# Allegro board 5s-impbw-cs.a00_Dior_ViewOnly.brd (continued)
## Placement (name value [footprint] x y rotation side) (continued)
PU7  -  [MX_QFN_20P_16_S118_PAD_4V]  110.82 61.81 90 top
PU8  -  [MX_QFN_16P_118X188_MPS]  119.6 6.59 270 bottom
PU9  -  [MX_SOT23_S5_H51]  46.91 11.39 270 bottom
Q1  -  [MX_SOT23]  52.9 65.16 0 bottom
Q2  -  [MX_SOT23_H43]  77.88 81.81 270 top
Q3  -  [MX_SOT363]  107.2 74.51 270 top
Q4  -  [MX_SOT23_H43]  116.1 67.62 270 bottom
Q5  -  [MX_SOT363]  181.63 68.02 90 bottom
Q6  -  [MX_SOT23_2D4_H51]  186.67 28.39 90 bottom
Q7  -  [MX_SOT363]  181.31 29.76 0 bottom
Q8  -  [MX_SOT23_H43]  127.37 81.66 270 top
Q9  -  [MX_SOT23_H43]  113.01 81.76 270 top
Q10  -  [MX_SOT23_H43]  115.51 72.71 270 top
Q11  -  [MX_SOT23_H43]  120.48 81.66 270 top
Q12  -  [MX_SOT23_H43]  111.14 72.7 270 top
Q13  -  [MX_SOT23_H43]  117.14 81.76 270 top
Q14  -  [MX_SOT23_H43]  123.79 81.66 270 top
Q15  -  [MX_SOT23_H43]  164.23 71.93 270 bottom
Q16  -  [MX_SOT23_H43]  167.46 71.93 270 bottom
Q19  -  [MX_SOT23_H43]  38.44 89.2 180 bottom
Q20  -  [MX_SOT23_H43]  11.13 73.5 90 bottom
Q21  -  [MX_SOT23_2D4_H44]  170.73 35.96 90 top
Q22  -  [MX_SOT23_H43]  173.5 31.9 270 top
Q23  -  [MX_SOT23_H43]  170.15 31.91 90 top
Q24  -  [MX_SOT23_2D4_H44]  178.18 70.95 0 bottom
Q25  -  [MX_SOT23_H43]  170.68 71.66 90 bottom
Q26  -  [MX_SOT23_H43]  173.93 71.66 90 bottom
Q27  -  [MX_SOT363]  173.08 69.38 0 top
Q28  -  [MX_SOT23_H43]  170.07 72.84 0 top
Q29  -  [MX_SOT363]  173.16 66.03 0 top
Q30  -  [MX_SOT363]  170.24 69.38 0 top
Q31  -  [MX_SOT363]  174.94 72.79 0 top
Q32  -  [MX_SOT23_H43]  177.91 72.35 90 top
Q33  -  [MX_SOT23_H43]  177.91 67.97 270 top
Q34  -  [MX_SOT23_H43]  61.31 9.69 180 bottom
Q35  -  [MX_SOT23_H43]  58.7 5.8 270 bottom
Q36  -  [MX_SOT23_H43]  160.31 38.94 90 top
Q37  -  [MX_SOT23_H43]  163.57 38.93 270 top
Q38  -  [MX_SOT23_H43]  119.35 67.97 270 bottom
Q39  -  [MX_SOT23_H43]  131.65 15.71 0 top
Q40  -  [MX_SOT363]  135.59 15.46 270 top
Q9200  -  [MX_SOT363]  156.57 61.3 90 top
Q9202  -  [MX_SOT23_H43]  144.57 78.87 90 top
R1  -  [MX_R0402]  74.53 49.17 180 top
R2  -  [MX_R0402]  76.76 47.46 270 top
R3  -  [MX_R0402]  84.2 45.74 90 top
R4  -  [MX_R0402]  76.99 49.45 0 top
R5  -  [MX_R0402]  78.82 44.09 90 top
R6  -  [MX_R0402]  83.72 50.23 0 top
R7  -  [MX_R0402]  80.82 48.28 270 top
R8  -  [MX_R0402]  81.87 48.28 270 top
R9  -  [MX_R0402]  75.67 47.46 270 top
R10  -  [MX_R0402]  88.75 50.46 0 top
R11  -  [MX_R0402]  88.75 51.5 0 top
R12  -  [MX_R0402]  73.28 47.57 270 top
R13  -  [MX_R0402]  88.75 47.26 0 top
R14  -  [MX_R0402]  77.83 47.46 270 top
R15  -  [MX_R0402]  88.75 48.33 0 top
R16  -  [MX_R0402]  88.75 45.03 0 top
R17  -  [MX_R0402]  88.75 46.12 0 top
R18  -  [MX_R0402]  86.97 43.15 270 top
R19  -  [MX_R0402]  79.69 49.32 270 top
R20  -  [MX_R0402]  85.45 44.01 270 top
R21  -  [MX_R0402]  73.89 44.59 180 top
R22  -  [MX_R0402]  88.75 49.39 0 top
R23  -  [MX_R0402]  88.72 43.15 270 top
R24  -  [MX_R0402]  73.89 43.5 180 top
R25  -  [MX_R0402]  77.74 44.09 90 top
R26  -  [MX_R0402]  78.65 49.57 270 top
R27  -  [MX_R0402]  70.85 49.41 270 top
R28  -  [MX_R0402]  71.94 49.41 270 top
R29  -  [MX_R0402]  81.41 50.23 0 top
R30  -  [MX_R0402]  86.64 29.43 0 top
R31  -  [MX_R0402]  81.26 44.11 90 top
R32  -  [MX_R0402]  90.83 58.08 270 top
R33  -  [MX_R0402]  86.64 70.81 0 top
R34  -  [MX_R0402]  86.64 30.45 0 top
R35  -  [MX_R0402]  80.21 44.11 90 top
R36  -  [MX_R0402]  90.8 60.38 90 top
R37  -  [MX_R0402]  86.64 71.9 0 top
R38  -  [MX_R0402]  86.98 22.39 90 top
R39  -  [MX_R0402_SHORT]  88.06 22.39 90 top
R40  -  [MX_R0402]  82.88 18.86 0 top
R41  -  [MX_R0402]  51.51 17.49 0 top
R42  -  [MX_R0402]  76.33 17.75 0 top
R43  -  [MX_R0402]  49.71 18.04 90 top
R44  -  [MX_R0402]  78.26 18.86 180 top
R45  -  [MX_R0402]  48.61 17.15 90 top
R46  -  [MX_R0402]  76.33 16.71 180 top
R47  -  [MX_R0402]  50.12 20.92 180 top
R56  -  [MX_R0402]  53.29 16.86 90 top
R57  -  [MX_R0402]  52.69 18.75 0 top
R59  -  [MX_R0402]  55.68 19.25 90 top
R60  -  [MX_R0402]  54.95 17.13 0 top
R61  -  [MX_R0402]  54.64 19.24 90 top
R62  -  [MX_R0402]  56.19 14.8 180 top
R63  -  [MX_R0402]  55.22 21.04 180 top
R66  -  [MX_R0402]  56.79 16.47 270 top
R69  -  [MX_R0402_SMALL]  169.55 80.03 270 bottom
R70  -  [MX_R0402_SMALL]  46.51 71.44 0 bottom
R71  -  [MX_R0402_SMALL]  24.87 74.03 270 bottom
R72  -  [MX_R0402_SMALL]  54.61 68.85 0 top
R73  -  [MX_R0402_SMALL]  48.46 68.8 180 top
R74  -  [MX_R0402]  48.59 69.82 180 top
R75  -  [MX_R0402_SMALL]  52.05 72.41 90 top
R76  -  [MX_R0402_SMALL]  52.16 68.34 0 top
R77  -  [MX_R0402]  48.77 67.85 0 top
R78  -  [MX_R0402_SMALL]  84.27 88.67 0 bottom
R79  -  [MX_R0402_SMALL]  29.57 71.7 90 top
R80  -  [MX_R0402_SMALL]  30.58 73.44 270 top
R81  -  [MX_R0402_SMALL]  28.12 74.15 270 bottom
R82  -  [MX_R0402_SMALL]  27.24 74.02 90 bottom
R83  -  [MX_R0402_SMALL]  35.47 74.45 90 bottom
R84  -  [MX_R0402_SMALL]  30.12 74.8 90 bottom
R85  -  [MX_R0402_SMALL]  30.41 71.7 90 top
R86  -  [MX_R0402_SMALL]  28.35 72.06 90 bottom
R87  -  [MX_R0402_SMALL]  27.28 71.92 90 bottom
R88  -  [MX_R0402_SMALL]  56.4 63.5 90 bottom
R89  -  [MX_R0402_SMALL]  56.41 66.41 90 bottom
R91  -  [MX_R0402_SMALL]  39.56 74.75 270 bottom
R92  -  [MX_R0402_SMALL]  26.41 74.02 270 bottom
R93  -  [MX_R0402_SMALL]  15.85 75.84 270 top
R94  -  [MX_R0402_SMALL]  16.67 75.84 270 top
R95  -  [MX_R0402_SMALL]  15.02 75.84 90 top
R96  -  [MX_R0402_SMALL]  26.46 71.92 90 bottom
R97  -  [MX_R0402_SMALL]  15.84 73.46 90 top
R98  -  [MX_R0402_SMALL]  16.67 73.46 90 top
R99  -  [MX_R0402_SMALL]  14.99 73.46 270 top
R103  -  [MX_R0402_SMALL]  23.87 71.84 90 bottom
R106  -  [MX_R0402_SMALL]  22.96 71.84 90 bottom
R108  -  [MX_R0402_SMALL]  43 61.69 0 top
R109  -  [MX_R0402_SMALL]  44.63 71.83 270 bottom
R110  -  [MX_R0402_SMALL]  27.13 71.75 90 top
R114  -  [MX_R0402_SMALL]  29.71 23.98 90 top
R119  -  [MX_R0402_SMALL]  43.81 71.83 270 bottom
R124  -  [MX_R0402_SMALL]  171.25 25.01 90 top
R125  -  [MX_R0402_SMALL]  171.25 23.39 270 top
R127  -  [MX_R0402_SMALL]  170.39 25.01 270 top
R128  -  [MX_R0402_SMALL]  170.4 23.39 90 top
R129  -  [MX_R0402]  159.39 34.15 180 top
R130  -  [MX_R0402]  159.55 14.32 90 top
R131  -  [MX_R0402]  160.76 32.17 270 top
R132  -  [MX_R0402]  170.61 26.87 180 top
R133  -  [MX_R0402_SMALL]  160.5 29.6 90 top
R134  -  [MX_R0402_SMALL]  161.85 32.22 270 top
R135  -  [MX_R0402]  168.59 19.86 180 top
R136  -  [MX_R0402_SMALL]  168.59 17.99 180 top
R137  -  [MX_R0402]  168.61 20.91 180 top
R138  -  [MX_R0402_SMALL]  168.62 18.89 180 top
R144  -  [MX_R0402_SMALL]  160.76 81.58 270 bottom
R145  -  [MX_R0402_SMALL]  171.35 84.12 0 top
R146  -  [MX_R0402_SMALL]  136.73 12.03 270 top
R148  -  [MX_R0402_SMALL]  7.27 81.09 270 top
R164  -  [MX_R0402_SMALL]  132.61 32.27 90 top
R165  -  [MX_R0402_SMALL]  131.75 32.28 270 top
R166  -  [MX_R0402_SMALL]  130.81 32.28 270 top
R167  -  [MX_R0402_SMALL]  129.09 32.31 270 top
R168  -  [MX_R0402_SMALL]  128.1 32.31 270 top
R169  -  [MX_R0402_SMALL]  127.23 32.31 270 top
R170  -  [MX_R0402_SMALL]  123.98 32.28 270 top
R171  -  [MX_R0402_SMALL]  123.06 32.28 270 top
R172  -  [MX_R0402_SMALL]  122.2 32.28 270 top
R173  -  [MX_R0402_SMALL]  107.14 80.99 0 top
R174  -  [MX_R0402]  104.17 75.93 0 top
R175  -  [MX_R0402]  102.92 81.35 0 top
R176  -  [MX_R0402_SMALL]  95.23 71.01 0 bottom
R177  -  [MX_R0402_SHORT_SMALL]  106.97 71.01 270 bottom
R178  -  [MX_R0402_SMALL]  95.56 79.54 0 top
R179  -  [MX_R0603_SMALL]  119.1 73 180 bottom
R180  -  [MX_R0603_SMALL]  115.03 85.03 90 top
R181  -  [MX_R0402_SMALL]  95.84 87.42 180 bottom
R182  -  [MX_R0402_SMALL]  95.56 78.72 0 top
R183  -  [MX_R0402_SMALL]  95.96 77.85 0 top
R184  -  [MX_R0402_SMALL]  104.52 81.25 90 top
R185  -  [MX_R0402_SMALL]  95.96 76.99 0 top
R186  -  [MX_R0402_SMALL]  95.96 76 0 top
R187  -  [MX_R0402_SHORT_SMALL]  93.68 81.6 180 top
R188  -  [MX_R0402_SMALL]  96.68 76.62 90 bottom
R189  -  [MX_R0402_SMALL]  93.8 83.41 180 bottom
R190  -  [MX_R0402_SMALL]  101.13 70.91 270 bottom
R191  -  [MX_R0402_SMALL]  102.84 71.01 90 bottom
R192  -  [MX_R0402_SHORT_SMALL]  93.68 82.45 180 top
R193  -  [MX_R0402_SMALL]  116.36 71.56 180 bottom
R194  -  [MX_R0402_SMALL]  116.36 70.64 180 bottom
R195  -  [MX_R0402_SMALL]  108.64 71.01 90 bottom
R196  -  [MX_R0402_SMALL]  107.8 71.01 90 bottom
R197  -  [MX_R0402_SMALL]  105.32 71.01 90 bottom
R198  -  [MX_R0402_SMALL]  104.5 71.01 90 bottom
R199  -  [MX_R0402_SMALL]  108.97 80.04 0 top
R200  -  [MX_R0402_SMALL]  108.97 79.13 0 top
R201  -  [MX_R0402_SMALL]  108.97 81.01 0 top
R202  -  [MX_R0402_SMALL]  103.68 71.01 90 bottom
R203  -  [MX_R0402_SMALL]  117.12 74.63 180 bottom
R204  -  [MX_R0402_SMALL]  117.12 73.59 180 bottom
R205  -  [MX_R0402_SMALL]  112.83 71.01 270 bottom
R206  -  [MX_R0402_SMALL]  101.64 74.09 90 top
R207  -  [MX_R0402_SMALL]  117.12 72.63 180 bottom
R208  -  [MX_R0402_SMALL]  102.68 74.09 270 top
R210  -  [MX_R0402_SMALL]  96.88 72.03 0 bottom
R211  -  [MX_R0402_SMALL]  96.88 72.86 180 bottom
R212  -  [MX_R0402_SMALL]  94.57 73.55 90 bottom
R213  -  [MX_R0402_SMALL]  111.99 71.02 90 bottom
R214  -  [MX_R0402_SMALL]  110.28 70.98 90 bottom
R215  -  [MX_R0402_SMALL]  111.15 71.02 90 bottom
R216  -  [MX_R0402_SMALL]  95.4 73.55 90 bottom
R217  -  [MX_R0402_SMALL]  98.91 80.03 180 top
R218  -  [MX_SHORTPIN_RECTANGLE_LF3]  114.25 63.61 270 bottom
R219  -  [MX_R0402_SMALL]  105.07 65.04 90 bottom
R220  -  [MX_R0402_SMALL]  105.12 67.2 90 bottom
R221  -  [MX_R0402_SMALL]  113.98 65.68 90 bottom
R222  -  [MX_R0402_SMALL]  109.46 70.77 270 bottom
R223  -  [MX_R0402_SMALL]  92.99 71.65 0 top
R224  -  [MX_R0402_SMALL]  117.53 75.91 270 bottom
R225  -  [MX_R0402_SMALL]  116.41 80.43 270 bottom
R226  -  [MX_R0402]  72.98 77.82 0 top
R227  -  [MX_R0402]  72.95 79 0 top
R228  -  [MX_R0402]  104.98 74.26 270 top
R229  -  [MX_R0402]  106.98 69.12 180 top
R230  -  [MX_R0402]  116.15 64.6 0 bottom
R231  -  [MX_R0805_SHORT_SMALL]  180.12 64.45 0 top
R232  -  [MX_R0402_SMALL]  183.57 62.95 270 top
R233  -  [MX_R0805_SHORT_SMALL]  181.84 58.84 270 top
R234  -  [MX_R0402_SMALL]  183.57 54.3 270 top
R235  -  [MX_R0402_SMALL]  183.8 67.5 270 bottom
R236  -  [MX_R0402_SMALL]  183.21 27.86 270 bottom
R237  -  [MX_R0402]  127.79 84.45 0 top
R238  -  [MX_R0402]  112.55 84.53 0 top
R239  -  [MX_R0402]  117.88 75.79 0 top
R240  -  [MX_R0402]  121.62 75.91 180 top
R241  -  [MX_R0402]  113.31 73.65 270 top
R242  -  [MX_R0402]  120.8 84.47 0 top
R243  -  [MX_R0402]  110.39 75.39 0 top
R244  -  [MX_R0402_SMALL]  109.17 68.96 0 top
R245  -  [MX_R0402]  117.63 84.47 0 top
R246  -  [MX_R0402]  124.28 84.47 0 top
R247  -  [MX_R0402_SMALL]  148.56 87.57 270 bottom
R248  -  [MX_R0402_SMALL]  148.56 89.15 270 bottom
R249  -  [MX_R0402]  148.46 80.84 90 bottom
R250  -  [MX_R0402_SMALL]  148.56 82.8 90 bottom
R251  -  [MX_R0402_SMALL]  167.16 68.39 180 bottom
R252  -  [MX_R0402_SMALL]  168.37 68.85 90 bottom
R253  -  [MX_R0402_SMALL]  164.24 68.37 180 bottom
R254  -  [MX_R0402_SMALL]  165.7 68.83 90 bottom
R255  -  [MX_R0402_SMALL]  166.7 74.57 0 bottom
R256  -  [MX_R0402_SMALL]  163.4 74.55 0 bottom
R257  -  [MX_R0402_SMALL]  167.16 69.24 0 bottom
R258  -  [MX_R0402_SMALL]  168.35 74.58 180 bottom
R259  -  [MX_R0402_SMALL]  164.24 69.21 0 bottom
R260  -  [MX_R0402_SMALL]  165.05 74.53 180 bottom
R273  -  [MX_R0603_SMALL]  37.69 86.56 180 bottom
R274  -  [MX_R0603_SMALL]  37.69 85.35 180 bottom
R275  -  [MX_R0402]  42.15 87.9 180 bottom
R276  -  [MX_R0402]  16.24 65.84 270 bottom
R277  -  [MX_R0402]  16.29 63.49 90 bottom
R278  -  [MX_R0402]  20.5 61.13 90 top
R279  -  [MX_R0402_SMALL]  103.05 19.84 180 top
R280  -  [MX_R0402_SMALL]  103.05 17.98 180 top
R281  -  [MX_R0402_SMALL]  103.05 18.85 180 top
R282  -  [MX_R0603_SHORT_SMALL]  102.92 8.15 90 bottom
R284  -  [MX_R0402_SHORT_SMALL]  153.45 11.98 90 top
R285  -  [MX_R0402_SHORT_SMALL]  152.54 11.98 90 top
R286  -  [MX_R0402_SMALL]  164.89 16.02 90 top
R288  -  [MX_R0402_SMALL]  174.21 18.18 90 top
R289  -  [MX_R0402]  174.21 15.92 90 top
R290  -  [MX_R0402_SMALL]  157.6 29.61 270 top
R291  -  [MX_R0402]  173.01 15.92 90 top
R293  -  [MX_R0402_SMALL]  173.02 18.18 90 top
R294  -  [MX_R0805_SMALL]  171.56 38.6 0 top
R295  -  [MX_R0805_SMALL]  167.64 12.18 180 top
R296  -  [MX_R0402]  169.61 14.01 90 top
R297  -  [MX_R0402_SMALL]  183.17 34.64 180 bottom
R298  -  [MX_R0402]  170.65 14.01 90 top
R299  -  [MX_R0603]  173.5 35.57 270 top
R300  -  [MX_R0402]  183.59 32.99 90 bottom
R301  -  [MX_R0402_SMALL]  158.6 29.59 90 top
R302  -  [MX_R0603]  181.05 33.24 270 bottom
R304  -  [MX_R0402]  182.45 32.99 270 bottom
R305  -  [MX_R0402]  175.39 62.78 0 top
R306  -  [MX_R0402_SMALL]  176.2 58.03 270 top
R307  -  [MX_R0402_SMALL]  177.45 56.71 270 top
R308  -  [MX_R0402_SMALL]  173.59 58.54 180 top
R309  -  [MX_R0402_SMALL]  173.59 59.38 180 top
R310  -  [MX_R0402_SMALL]  175.95 72.92 90 bottom
R311  -  [MX_R0402_SMALL]  175.94 71.29 270 bottom
R312  -  [MX_L1206_H51]  176.68 66.11 270 bottom
R313  -  [MX_R0402]  172.88 72.41 270 top
R314  -  [MX_R0402]  168.3 70.02 90 top
R315  -  [MX_R0402]  175.06 67.61 90 top
R316  -  [MX_R0402]  171.17 66.08 90 top
R318  -  [MX_R0402]  170 66.08 90 top
R319  -  [MX_R0402]  174.19 75.02 180 top
R320  -  [MX_R0402]  180.17 71.65 270 top
R321  -  [MX_R0402]  175.77 69.77 90 top
R322  -  [MX_R0402]  180.06 69.13 90 top
R323  -  [MX_R0402_SMALL]  20.17 84.76 180 top
R324  -  [MX_R0402_SMALL]  20.17 85.59 180 top
R325  -  [MX_R0402_SMALL]  29.26 83.46 90 top
R326  -  [MX_R0402_SMALL]  27.67 83.07 180 top
R327  -  [MX_R0402_SMALL]  20.03 81.98 270 top
R328  -  [MX_R0402_SMALL]  20.92 81.98 270 top
R329  -  [MX_R0402_SMALL]  27.92 84.96 0 top
R330  -  [MX_R0402_SMALL]  27.92 84.13 0 top
R331  -  [MX_R0402_SMALL]  31.71 81.17 90 top
R332  -  [MX_R0402_SMALL]  40.92 85.04 180 top
R333  -  [MX_R0402_SMALL]  40.77 83.8 180 top
R334  -  [MX_R0402_SMALL]  39.6 82.81 180 top
R335  -  [MX_R0402_SMALL]  30.8 83.24 180 top
R336  -  [MX_R0402_SMALL]  30.8 82.39 180 top
R337  -  [MX_R0402_SMALL]  39.12 85.2 0 top
R338  -  [MX_R0402_SMALL]  39.12 83.89 0 top
R339  -  [MX_R0402_SMALL]  59.05 11.79 180 bottom
R340  -  [MX_R0402_SMALL]  58.18 8.42 0 bottom
R341  -  [MX_R0402_SMALL]  60.86 6.99 270 bottom
R342  -  [MX_R0402_SMALL]  61.25 5.64 0 bottom
R343  -  [MX_R0402_SMALL]  157.68 36.29 180 top
R344  -  [MX_R0402_SMALL]  161.62 36.29 0 top
R345  -  [MX_R0402_SMALL]  161.69 41.64 180 top
R346  -  [MX_R0402_SMALL]  163.4 36.29 0 top
R347  -  [MX_R0402]  122.12 70.91 90 bottom
R348  -  [MX_R0402_SMALL]  123.06 70.91 270 bottom
R349  -  [MX_R0402]  131.27 12.16 90 top
R350  -  [MX_R0402]  133.55 12.16 270 top
R351  -  [MX_R0402_SMALL]  134.7 12.03 270 top
R352  -  [MX_R0402_SMALL]  135.71 12.03 270 top
R353  -  [MX_R0402]  132.41 12.16 90 top
R354  -  [MX_R0402_SMALL]  178.21 80.15 90 bottom
R355  -  [MX_R0402_SMALL]  177.55 81.86 0 bottom
R356  -  [MX_R0402_SMALL]  178.16 77.77 270 bottom
R357  -  [MX_R0402_SMALL]  179.15 81.86 0 bottom
R358  -  [MX_R0402_SMALL]  179.02 75.58 270 bottom
R359  -  [MX_R0402_SMALL]  179.53 78.33 180 bottom
R360  -  [MX_R0402_SMALL]  175.34 84.37 270 bottom
R369  -  [MX_R0402_SMALL]  150.37 77.28 0 bottom
R370  -  [MX_R0402_SMALL]  159.03 67.96 90 top
R371  -  [MX_R0402_SMALL]  158.17 67.96 90 top
R376  -  [MX_R0402_SMALL]  182.96 49.34 180 top
R377  -  [MX_R0402]  180.7 52.93 0 top
R378  -  [MX_R0402_SMALL]  170.26 52.93 0 top
R379  -  [MX_R0402_SMALL]  170.26 49.88 0 top
R380  -  [MX_R0402_SMALL]  170.26 50.89 0 top
R381  -  [MX_R0402_SMALL]  170.26 51.91 0 top
R382  -  [MX_R0402_SMALL]  173.05 52.93 180 top
R383  -  [MX_R0402_SMALL]  173.05 49.88 180 top
R384  -  [MX_R0402_SMALL]  173.05 50.89 180 top
R385  -  [MX_R0402_SMALL]  173.05 51.91 180 top
R386  -  [MX_R0402_SMALL]  182.96 50.18 180 top
R387  -  [MX_R0402_SMALL]  182.96 51.07 180 top
R388  -  [MX_R0402_SMALL]  180.71 51.02 0 top
R389  -  [MX_R0402_SMALL]  180.71 51.91 0 top
R400  -  [MX_R0402_SMALL]  34.95 72.02 90 bottom
R401  -  [MX_R0402_SMALL]  28.73 71.7 90 top
R405  -  [MX_R0402_SMALL]  40.44 74.74 270 bottom
R406  -  [MX_R0402]  41.66 72.2 90 bottom
R407  -  [MX_R0402]  39.07 72.24 90 bottom
R410  -  [MX_R0402]  138.13 74.05 270 top
R414  -  [MX_R0402_SMALL]  161.6 85.4 0 top
R415  -  [MX_R0402_SMALL]  22.98 74.29 270 bottom
R416  -  [MX_R0402_SMALL]  21.99 76.97 270 top
R425  -  [MX_R0402_SMALL]  24.81 81.38 180 bottom
R426  -  [MX_R0402_SMALL]  149.9 7.13 0 top
R427  -  [MX_R0402_SMALL]  183.72 14.91 90 bottom
R428  -  [MX_R0402_SMALL]  161.05 73.29 270 top
R429  -  [MX_R0402_SMALL]  150.64 71.23 180 bottom
R430  -  [MX_R0402_SMALL]  157.93 74.81 270 top
R431  -  [MX_R0402]  160.1 68.04 270 top
R432  -  [MX_R0402]  167.38 67.2 90 top
R433  -  [MX_R0402]  172.04 62.61 0 top
R434  -  [MX_R0402_SMALL]  80.33 87.88 180 bottom
R435  -  [MX_R0402_SMALL]  77.62 87.17 180 bottom
R436  -  [MX_R0402]  165.69 66.77 0 top
R437  -  [MX_R0603]  123.19 68.95 180 top
R440  -  [MX_R0402_SMALL]  121.36 32.28 270 top
R450  -  [MX_R0402_SMALL]  175.78 56.51 180 top
R455  -  [MX_R0402_SMALL]  101.98 70.91 90 bottom
R456  -  [MX_R0402_SMALL]  99.75 70.49 0 bottom
R457  -  [MX_R0402_SMALL]  116.72 77.16 0 bottom
R9203  -  [MX_R0402_SMALL]  139.53 77.04 0 top
R9204  -  [MX_R0402_SMALL]  153.26 65.03 90 top
R9330  -  [MX_R0402_SMALL]  32.9 72.35 270 bottom
R60358  -  [MX_R0402_SMALL]  156.61 29.61 270 top
R60359  -  [MX_R0402_SMALL]  10.25 75.73 270 top
R60362  -  [MX_R0402_SMALL]  11.3 76.15 270 top
R60364  -  [MX_R0402]  12.52 75.57 90 top
R60365  -  [MX_R0402]  14.02 75.6 90 top
R60368  -  [MX_R0402_SMALL]  154.94 78.46 180 bottom
R60369  -  [MX_R0402_SMALL]  154.94 79.38 180 bottom
R60370  -  [MX_R0402_SMALL]  155.23 68.05 90 top
R60371  -  [MX_R0402_SMALL]  154.32 68.05 90 top
R60464  -  [MX_R0402_SMALL]  32.42 74.22 90 bottom
R60465  -  [MX_R0402]  139.42 78.03 0 top
R60466  -  [MX_R0402]  139.56 79.19 180 top
R60467  -  [MX_R0402]  139.56 80.28 180 top
R60468  -  [MX_R0402]  139.56 81.38 180 top
R60469  -  [MX_R0402]  138.13 76.38 270 top
R60471  -  [MX_R0402_SMALL]  128.94 44.97 270 top
R60472  -  [MX_R0402_SMALL]  173.13 56.46 90 top
R60473  -  [MX_R0402_SMALL]  173.99 56.46 90 top
R60474  -  [MX_R0402_SMALL]  8.51 85.56 0 top
R60475  -  [MX_R0402_SMALL]  8.51 84.68 0 top
R60476  -  [MX_R0402_SMALL]  178.28 56.71 270 top
R60477  -  [MX_R0402_SMALL]  24.08 9.85 180 bottom
RN1  -  [MX_2R4P0402]  48.03 72.88 180 top
RN3  -  [MX_2R4P0402]  49.65 72.82 180 top
RN4  -  [MX_4R8P0402]  25.37 71.78 180 top
RN6  -  [MX_2R4P0603]  161.68 85.34 180 bottom
RN7  -  [MX_2R4P0603]  33.95 89.04 90 bottom
RN8  -  [MX_2R4P0402_H18]  44.38 70.58 0 top
S1C1  -  [MX_C0402]  165.51 46.74 180 top
S1C2  -  [MX_C0402]  165.51 47.92 180 top
S1C3  -  [MX_C0402]  167.76 49.23 0 top
S1C4  -  [MX_C0402]  167.76 50.33 0 top
S1C5  -  [MX_C0402]  167.77 51.47 0 top
S1C6  -  [MX_C0402]  167.77 52.61 0 top
S1C7  -  [MX_C0402]  167.74 53.71 180 top
S1C8  -  [MX_C0402]  167.74 54.78 180 top
S1C9  -  [MX_C0402]  167.74 55.91 180 top
S1C10  -  [MX_C0402]  167.74 57 180 top
S1R4  -  [MX_R0402]  162.14 46.76 0 top
S1R5  -  [MX_R0402]  162.13 47.91 180 top
SC1  -  [MX_C0402_SMALL]  34.05 67.87 90 top
SC2  -  [MX_C0402_SMALL]  93.68 79.98 180 top
SC3  -  [MX_C0402_SMALL]  99.93 72.59 0 bottom
SC4  -  [MX_C0402_SMALL]  95.8 84.69 0 bottom
SC5  -  [MX_C0402_SMALL]  97.03 82.14 0 bottom
SC6  -  [MX_C0402_SMALL]  114.73 75.94 180 top
SC7  -  [MX_C0402]  102.49 11.12 180 bottom
SC8  -  [MX_C0402_SMALL]  180.85 54.7 180 top
SC9  -  [MX_C0402_SMALL]  180.84 53.87 180 top
SC10  -  [MX_C0402_SMALL]  180.27 59.5 270 top
SC11  -  [MX_C0402_SMALL]  179.4 59.5 270 top
SC12  -  [MX_C0402]  175.54 62.91 0 bottom
SC13  -  [MX_C0402_SMALL]  22.93 81.07 270 top
SC14  -  [MX_C0402_SMALL]  16.03 83.28 0 top
SC15  -  [MX_C0402_SMALL]  23.77 81.07 270 top
SC16  -  [MX_C0402_SMALL]  16.03 84.09 0 top
SC17  -  [MX_C0402_SMALL]  24.7 81.04 90 top
SC18  -  [MX_C0402_SMALL]  25.61 81.04 90 top
SC19  -  [MX_C0402_SMALL]  33.85 79.78 90 top
SC20  -  [MX_C0402_SMALL]  31.08 86.24 0 top
SC21  -  [MX_C0402_SMALL]  34.71 79.78 90 top
SC22  -  [MX_C0402_SMALL]  31.08 87.06 0 top
SC23  -  [MX_C0402_SMALL]  35.78 79.64 270 top
SC24  -  [MX_C0402_SMALL]  36.64 79.64 270 top
SP1  -  [MX_R0402_SHORT_SMALL]  117.27 85.87 180 bottom
SQ1  -  [MX_SOT363]  69.78 88.21 90 bottom
SQ2  -  [MX_SOT363]  73.49 88.21 270 bottom
SR1  -  [MX_R0402_SMALL]  55.02 63.14 180 bottom
SR2  -  [MX_R0402_SMALL]  55.55 66.34 90 bottom
SR3  -  [MX_R0402]  29.73 72.19 270 bottom
SR4  -  [MX_R0402]  22.04 74.68 90 bottom
SR7  -  [MX_R0402]  10.62 72.1 180 top
SR8  -  [MX_R0402]  29.19 75.32 90 bottom
SR9  -  [MX_R0402_SMALL]  84.14 87.84 180 bottom
SR10  -  [MX_R0402]  17.96 52.68 270 top
SR13  -  [MX_R0402_SMALL]  32.19 74.8 270 top
SR14  -  [MX_R0402_SMALL]  27.15 73.4 270 top
SR15  -  [MX_R0402]  19.61 24.96 180 top
SR16  -  [MX_R0402]  23.01 74.22 270 top
SR18  -  [MX_R0402]  19.2 23.18 90 top
SR19  -  [MX_R0402]  50.45 56.38 0 bottom
SR21  -  [MX_R0402]  23.56 71.7 90 top
SR27  -  [MX_R0402]  30.91 72.46 270 bottom
SR28  -  [MX_R0402]  34.88 77.18 270 top
SR29  -  [MX_R0402_SMALL]  103.56 74.08 270 top
SR35  -  [MX_R0402]  32.81 71.82 270 top
SR36  -  [MX_R0402]  42.15 76.3 270 top
SR50  -  [MX_R0402]  23.91 74.19 270 bottom
SR51  -  [MX_R0402]  35.44 76.76 90 bottom
SR52  -  [MX_R0402]  33.78 72.18 270 bottom
SR59  -  [MX_R0402]  36.47 76.75 270 bottom
SR60  -  [MX_R0402]  34.44 74.82 90 bottom
SR61  -  [MX_R0402]  30.42 78.56 90 bottom
SR62  -  [MX_R0402]  32.49 78.56 270 bottom
SR63  -  [MX_R0402]  31.46 78.56 90 bottom
SR70  -  [MX_R0402]  43.84 78.38 270 top
SR71  -  [MX_R0402]  66.96 87.42 180 bottom
SR72  -  [MX_R0402]  70.87 90.11 0 bottom
SR73  -  [MX_R0402]  69.57 86.38 0 bottom
SR74  -  [MX_R0402]  68.43 90.11 180 bottom
SR75  -  [MX_R0402]  73.43 90.11 0 bottom
SR76  -  [MX_R0402]  73.1 86.3 180 bottom
SR77  -  [MX_R0402_SMALL]  159.92 81.58 90 bottom
SR78  -  [MX_R0402_SMALL]  42.98 71.87 90 bottom
SR79  -  [MX_R0402_SMALL]  41.72 74.45 270 bottom
SR80  -  [MX_R0402_SMALL]  41.22 76.04 270 top
SR81  -  [MX_R0402_SMALL]  41.88 72.26 270 top
SR82  -  [MX_R0402_SMALL]  37.09 72.12 270 bottom
SR85  -  [MX_R0402]  23.38 76.9 270 top
SR86  -  [MX_R0402]  22.49 71.69 90 top
SR87  -  [MX_R0402]  21.43 71.69 270 top
SR88  -  [MX_R0402]  24.08 74.2 270 top
SR89  -  [MX_R0402]  19.29 71.65 90 top
SR90  -  [MX_R0402]  19.35 73.95 270 top
SR97  -  [MX_R0402]  48.11 78.64 90 top
SR9206  -  [MX_R0402_SHORT_SMALL]  156.82 64.25 180 top
SR9208  -  [MX_R0402_SMALL]  164.25 85.82 180 top
SR9209  -  [MX_R0402]  26.06 75.26 90 top
SR9210  -  [MX_R0402]  31.4 60.31 270 top
ST1  -  [MX_TPC26B_S4_68]  21.82 60.52 180 bottom
ST2  -  [MX_TPC26B_S4_68]  21.79 62.32 180 bottom
ST3  -  [MX_TPC26B_S4_68]  31.78 49.34 180 bottom
ST4  -  [MX_TPC26B_S4_68]  32.31 54.93 180 bottom
ST8  -  [MX_TPC26B_S4_68]  186.44 26.04 0 top
ST9  -  [MX_TPC26B_S4_68]  111.56 52.14 0 top
ST14  -  [MX_TPC26B_S4_68]  25.66 65.4 180 bottom
ST15  -  [MX_TPC26B_S4_68]  27.38 66.24 180 bottom
ST16  -  [MX_TPC26B_S4_68]  25.07 70.86 0 top
ST18  -  [MX_TPC26B_S4_68]  26.57 67.86 180 bottom
ST19  -  [MX_TPC26B_S4_68]  23.67 68.19 180 bottom
ST20  -  [MX_TPC26B_S4_68]  21.64 70.83 0 top
ST21  -  [MX_TPC26B_S4_68]  25.02 67.01 180 bottom
ST22  -  [MX_TPC26B_S4_68]  23.75 69.97 180 bottom
ST24  -  [MX_TPC26B_S4_68]  23.78 65.47 180 bottom
ST27  -  [MX_TPC26B_S4_68]  20.17 69.92 180 bottom
ST28  -  [MX_TPC26B_S4_68]  21.67 72.71 0 top
ST29  -  [MX_TPC26B_S4_68]  33.86 82.39 0 top
ST30  -  [MX_TPC26B_S4_68]  123.39 38.45 0 top
ST31  -  [MX_TPC26B_S4_68]  125.3 38.96 0 top
ST32  -  [MX_TPC26B_S4_68]  120.73 40.99 0 top
ST33  -  [MX_TPC26B_S4_68]  141.56 73.63 0 top
ST34  -  [MX_TPC26B_S4_68]  5.92 68.8 0 top
ST35  -  [MX_TPC26B_S4_68]  5.67 54.07 0 top
ST36  -  [MX_TPC26B_S4_68]  5.67 52.04 0 top
ST37  -  [MX_TPC26B_S4_68]  5.54 49.12 0 top
ST38  -  [MX_TPC26B_S4_68]  15.44 35.53 180 bottom
ST39  -  [MX_TPC26B_S4_68]  11.63 35.91 180 bottom
ST40  -  [MX_TPC26B_S4_68]  135.71 58.26 180 bottom
ST41  -  [MX_TPC26B_S4_68]  111.58 50.13 0 top
ST42  -  [MX_TPC26B_S4_68]  137.36 39.72 0 top
ST43  -  [MX_TPC26B_S4_68]  179.02 65.75 0 top
SW1  -  [MX_SW_5P_315X244_H98]  151.76 82.46 0 top
T1  -  [MX_TPC26B_S4_68]  50.57 67.84 180 bottom
T2  -  [MX_TPC26B_S4_68]  46.25 65.12 0 top
T3  -  [MX_TPC26B_S4_68]  46.86 69 180 bottom
T4  -  [MX_TPC26B_S4_68]  25.3 55.24 180 bottom
T5  -  [MX_TPC26B_S4_68]  27.03 54.93 180 bottom
T8  -  [MX_TPC26B_S4_68]  31.93 67.68 180 bottom
T9  -  [MX_TPC26B_S4_68]  26.84 63.09 180 bottom
T10  -  [MX_TPC26B_S4_68]  25.79 75.4 0 top
T25  -  [MX_TPC26B_S4_68]  111.13 78.68 180 bottom
T27  -  [MX_TPC26B_S4_68]  109.27 89.1 180 bottom
T28  -  [MX_TPC26B_S4_68]  111.02 89.12 180 bottom
T29  -  [MX_TPC26B_S4_68]  182.42 65.42 0 top
T30  -  [TPC85B_68]  181.31 18.38 0 top
T31  -  [MX_TPC26B_S4_68]  186.89 23.28 180 bottom
T32  -  [MX_TPC26B_S4_68]  172.01 67.51 0 top
T33  -  [MX_TPC26B_S4_68]  40.36 87.01 0 top
T34  -  [TPC85B_68]  137.57 69.66 180 bottom
T35  -  [MX_TPC26B_S4_68]  20.76 80.49 180 bottom
T36  -  [MX_TPC26B_S4_68]  27.15 82.01 180 bottom
T37  -  [MX_TPC26B_S4_68]  31.64 82.24 0 top
T38  -  [MX_TPC26B_S4_68]  39.04 81.45 0 top
T39  -  [MX_TPC26B_S4_68]  133.17 72.41 180 bottom
T40  -  [MX_TPC26B_S4_68]  133.45 74.26 180 bottom
T41  -  [MX_TPC26B_S4_68]  137.39 75.02 0 top
T42  -  [MX_TPC26B_S4_68]  135.87 72.18 180 bottom
T43  -  [MX_TPC26B_S4_68]  128.58 76.47 180 bottom
T44  -  [MX_TPC26B_S4_68]  128.55 78.63 180 bottom
T45  -  [MX_TPC26B_S4_68]  127.03 75.67 180 bottom
T46  -  [MX_TPC26B_S4_68]  128.02 4.56 0 top
T47  -  [MX_TPC26B_S4_68]  124.66 4.06 0 top
T48  -  [MX_TPC26B_S4_68]  141.05 10.51 0 top
T49  -  [MX_TPC26B_S4_68]  139.22 10.51 0 top
T50  -  [MX_TPC26B_S4_68]  142.85 10.46 0 top
T51  -  [MX_TPC26B_S4_68]  125.5 78.55 180 bottom
T52  -  [MX_TPC26B_S4_68]  139.27 73.63 0 top
T53  -  [TPC85B_68]  114.63 36.16 0 top
T54  -  [MX_TPC26B_S4_68]  107.44 79.62 180 bottom
T58  -  [MX_TPC26B_S4_68]  129.06 71.62 180 bottom
T59  -  [MX_TPC26B_S4_68]  118.49 70.73 180 bottom
T60  -  [MX_TPC26B_S4_68]  119.28 68.95 180 bottom
T61  -  [MX_TPC26B_S4_68]  137.71 47.09 180 bottom
T62  -  [MX_TPC26B_S4_68]  32.79 69.31 180 bottom
T63  -  [MX_TPC26B_S4_68]  34.06 70.35 0 top
T65  -  [MX_TPC26B_S4_68]  16.92 60.98 180 bottom
T70  -  [MX_TPC26B_S4_68]  17.53 64.97 180 bottom
T71  -  [MX_TPC26B_S4_68]  178.26 82.02 180 bottom
T72  -  [MX_TPC26B_S4_68]  176.86 77.82 180 bottom
T9200  -  [MX_TPC26B_S4_68]  136.86 74.64 180 bottom
T9206  -  [MX_TPC26B_S4_68]  158.29 64.61 180 bottom
T9207  -  [MX_TPC26B_S4_68]  152.25 65.3 180 bottom
T9208  -  [TPC85B_68]  173.6 76.24 0 top
U1  -  [MX_BGA_1168P_30_1575X945]  31.83 48.49 90 bottom
U2  -  [MX_BGA_96P_31_524X433_COLAY]  77.98 25.41 0 top
U3  -  [MX_BGA_96P_31_524X433_COLAY]  77.98 36.94 0 top
U4  -  [MX_BGA_96P_31_524X433_COLAY]  77.98 56.75 0 top
U5  -  [MX_BGA_96P_31_524X433_COLAY]  77.98 68.29 0 top
U6  -  [MX_QFN_64P_16_S315_PAD_ANA]  162.29 22.92 180 top
U9  -  [MX_SOIC_28P_26_386X252]  127.95 38.64 180 top
U10  -  [MX_QFP_128P_16_630X630]  106.78 81.93 90 bottom
U11  -  [MX_SOIC_8P_50_197X236]  109.62 66.96 90 bottom
U12  -  [MX_SOIC_8P_26_122X193_H48]  74.22 82.98 180 top
U13  -  [MX_QFN_24P_20_S157_PAD_IN]  24.08 85.04 270 top
U14  -  [MX_QFN_24P_20_S157_PAD_IN]  34.96 83.41 270 top
U15  -  [MX_WTOB_5P_59_RA_F_ACES]  12.67 54.08 90 bottom
U16  -  [MX_LGA_16P_20_118X118_ST]  163.63 83.18 0 top
U17  -  [MX_LGA_16P_20_118X118_ST]  159.59 83.15 0 top
U19  -  [MX_LGA_16P_20_S118_H47]  156.39 55.54 270 top
U20  -  [MX_QFP_48P_20_354X354_H63]  157.18 72.56 90 bottom
U21  -  [MX_QFN_20P_20_S157_P83_4V]  176.73 51.4 0 top
U22  -  [MX_ANT_CLIP_1P_102X107]  125.74 36.67 180 bottom
U23  -  [MX_ANT_CLIP_1P_102X107]  113.98 39.19 180 bottom
U24  -  [MX_ANT_CLIP_1P_102X107]  123.71 41.11 180 bottom
U25  -  [MX_ANT_CLIP_1P_102X107]  107.36 60.51 180 bottom
UA3  -  [MX_LGA_16P_26_157X157_H39]  162.12 56.15 90 top
V1C21  -  [MX_C0603_SMALL]  159.24 32.45 270 top
VCB1  -  [MX_C0402_SMALL]  147.5 90.38 180 bottom
VCB2  -  [MX_C0402_SMALL]  147.14 80.16 180 bottom
VCB3  -  [MX_C0402_SMALL]  178.65 35.93 90 bottom
VCB4  -  [MX_C0402_SMALL]  178.65 37.86 270 bottom
VCB5  -  [MX_C0402_SMALL]  188.29 33.49 90 bottom
VR1  -  [MX_R0402_SMALL]  181.54 27.44 180 bottom
VR2  -  [MX_R0402]  151.49 11.93 90 top
VU1  -  [MX_SOT23_S5_H57]  146.37 87.6 270 bottom
VU2  -  [MX_SOT23_S5_H57]  146.13 82.92 90 bottom
VU3  -  [MX_SOT23_S5_H57]  181.46 36.95 0 bottom
VU4  -  [MX_SOT23_S5_H57]  175.87 36.94 180 bottom
VU5  -  [MX_SOT23_S5_H57]  186.01 33.11 270 bottom
X1  -  [MX_XTAL_4P_272X55]  46.94 76.95 90 bottom
X2  -  [MX_XTAL_4P_272X55]  95.18 78.9 90 bottom
X3  -  [MX_XTAL_2P_126X59_CITIZEN]  147.43 72.36 90 bottom
XDP1  -  [MX_SCONN60_EPG082001]  74.53 6.82 0 top

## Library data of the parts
AC1-AC4 C134 C136 C142 CKC1-CKC4 CKC7 SC7 SC12 = DEV_73
AR1-AR4 = DEV_235
AT2-AT4 AT6 AT9 H19 HT1-HT58 HT60-HT63 HT65-HT68 HT70-HT72 HT81-HT87 HT89-HT99 PT2 PT4 PT6-PT8 ST1-ST4 ST8 ST9 ST14-ST16 ST18-ST22 ST24 ST27-ST43 T1-T5 T8-T10 T25 T27-T29 T31-T33 T35-T52 T54 T58-T63 T65 T70-T72 T9200 T9206 T9207 = DEV_108
C1 C53-C57 C68 C85 C176 C180 C199 C200 C431-C433 C9207 C9209 C9212-C9215 C9220 CB3 CB5 VCB1-VCB5 = DEV_233
C2-C9 C91 C94 C112 C138 C139 CA13 D3CE2-D3CE9 D3CE40 D3CE41 PC150 PC156-PC158 PC182 PC187 PC194 PC201 PC213 PC218 PC224 V1C21 = DEV_82
C10-C41 C195 D3CE20-D3CE27 D3CE36-D3CE39 GC1 HC6 PC3 PC4 PC6 PC10 PC12 PC15 PC16 PC19 PC20 PC23-PC26 PC28 PC30 PC31 PC34-PC40 PC220 = DEV_80
C42 C43 C45 C46 = DEV_189
C48 C51 C52 C88 C147 = DEV_81
C49 C50 CKC5 CKC6 = DEV_297
C58 C59 C9210 C9211 = DEV_232
C60 C1180-C1183 C9206 D3C5 = DEV_234
C61-C66 C69-C72 C74 C76-C78 C82-C84 C87 C97-C99 C101 C163 C165 C171 C173 C178 C179 C181-C185 C190-C194 CA10 HC8 MC1-MC4 PC73 PC124 PC128 PC136 PC138 PC141 PC155 PC159 PC177 PC197 SC8-SC11 SC13-SC24 = DEV_78
C67 C116 C128-C131 C153 C156 C159-C161 C186 C187 C201 PC69 = DEV_71
C73 C75 C152 C155 PC67 PC68 = DEV_61
C79 = DEV_76
C80 C81 = DEV_98
C86 PC55 = DEV_3
C92 C93 C95 C96 = DEV_79: room: SATA
C100 = DEV_60
C102 C103 = DEV_103
C111 C113 C140 C141 D3C7 D3C8 PC77 PC78 PC171 S1C1-S1C10 = DEV_79
C114 C132 C133 C135 C137 C144-C146 C151 C154 C157 C158 C177 C400 PC57 PC60 PC61 PC65 PC70-PC72 PC185 = DEV_52
C115 C125 C148 C162 C164 C172 C1174-C1179 = DEV_70
C121-C124 C127 C150 CA11 PC46 PC58 PC186 PC190 = DEV_56
C126 C149 = DEV_78: room: AUD
C143 = DEV_72
C196-C198 C420 C9217-C9219 GC2 PC80 = DEV_77
C430 PC162 PC170 = DEV_95
C1184-C1191 = DEV_242
C1192 = DEV_302
C1193 C1194 GC3 GC4 HC1 HC7 PC8 PC9 PC17 PC18 PC33 PC43 = DEV_221
C1195 = DEV_226
C9200 = DEV_253: room: CTL
CA12 CB7 PC52 PC53 PC91 PC115 PC148 PC184 PC188 PC200 PC223 PC225 = DEV_68
CB1 CB2 CB4 CB6 = DEV_102
CE1 = DEV_238
CKR1 PR50 R130 = DEV_231
CKR2 PR115 SR7 SR10 = DEV_230
CKR3-CKR5 = DEV_229
CKRN1 CKRN2 RN8 = DEV_118
CKX1 = DEV_228
CN1 = DEV_67
CON1 = DEV_122
CON2 = DEV_317
CON3 = DEV_132
CON4 = DEV_267
CON5 = DEV_272
CON6 = DEV_124
CON7 = DEV_263
CON8 = DEV_116
CON9 = DEV_131
CON10 = DEV_105
CON11 = DEV_117
CONSATA = DEV_311
CONWIFI = DEV_199
CR1-CR9 = DEV_96
CX3 CX4 = DEV_77: room: NB_
D1 D9201 PD3 PD4 = DEV_65
D2 D4 D6 D7 D13 D14 D24 = DEV_63
D3CE28 PCE7 = DEV_241
D5 D10-D12 D16 D20-D22 = DEV_66
D8 = DEV_64
D9 = DEV_138
D15 D18 = DEV_141
D17 D19 = DEV_139
D9200 = DEV_63: room: CTL
DIMM1 = DEV_240
E2 = DEV_142
F1 = DEV_126
F3CB4 PC75 PC92 PC117 PC119 PC160 PC174-PC176 PC195 = DEV_196
F3J1 = DEV_298
F3R2 F3R3 F3R13 F3R14 GR4 GR6 GR7 GR14 GR22 GR31 HR37-HR42 PR12 PR107 PR109 PR110 PR162 PR163 PR200 SR18 SR27 SR28 SR86 SR87 SR89 SR90 = DEV_100
F3R7-F3R11 = DEV_223
F3U1 = DEV_286
GR1-GR3 GR5 GR28-GR30 GR37 = DEV_220
GR8 GR10-GR13 GR15-GR21 GR23 GR27 HR3 HR6 HR12 PR15 PR26 PR31 PR33 PR35-PR37 PR40 PR41 PR43-PR46 PR102 PR117 PR154 PR155 PR171 PR179 PR180 PR197 PR203 PR209 PR217 PR220 PR221 PR227-PR229 PR231 PR232 PR242 PR243 R410 R60465-R60469 SR15 SR73-SR76 SR85 = DEV_24
GR24 GR26 HR5 HR31 HR46 HR47 PR7 PR16 PR18 PR20 PR29 PR30 PR54 PR77 R129 R226-R228 R276 R278 R289 R291 R300 SR3 SR4 SR8 SR35 SR36 SR50-SR52 SR59-SR63 SR70 SR88 SR9209 SR9210 = DEV_25
GR25 = DEV_219
GR32-GR34 = DEV_218
GR35 GR36 GR38 HR9 PR49 = DEV_217
GR39 PR101 PR104 PR105 PR118 PR121 PR130 PR131 R277 R349 R350 R353 = DEV_7
GU1 = DEV_216
GU2 HU1 HU4 = DEV_215
H1-H4 = DEV_114
H9 H11 = DEV_115
H6505 = DEV_262
H6506 = DEV_261
H6507 H6508 = DEV_260
H6509 = DEV_259
H6510 = DEV_287
H6511 = DEV_296
H6512 = DEV_295
HC3 = DEV_310
HC5 PC7 PC11 PC13 PC14 PC27 PC29 PC32 = DEV_214
HQ1-HQ3 PQ7 PQ8 PQ28 Q8-Q11 Q13-Q16 Q19 Q20 Q25 Q26 Q28 Q32-Q34 Q36 Q38 Q39 Q9202 = DEV_48
HR2 = DEV_209
HR4 = DEV_205
HR7 = DEV_202
HR8 = DEV_201
HR10 HR11 = DEV_213
HR13 = DEV_212
HR14 HR15 = DEV_211
HR16 R46 R47 R62 R63 = DEV_210
HR21 HR27-HR29 PR3 PR10 PR11 PR14 PR21 PR22 PR24 PR216 R39 = DEV_316
HR22 = DEV_208
HR23 = DEV_207
HR24 = DEV_206
HR32-HR34 PR32 PR42 = DEV_222
HR43 HR44 SR19 = DEV_204
HR45 = DEV_203
HR48 R208 R212 R247 R250 R257-R260 R286 R288 R290 R293 R297 R301 R356-R360 R60474 R60475 = DEV_44
J1 = DEV_112
L2 L3 = DEV_200
L4 = DEV_129
L5 L6 = DEV_62
L7-L11 = DEV_119
P2 = DEV_121
PC21 = DEV_192
PC42 = DEV_191
PC44 PC45 PC47 = DEV_55
PC48-PC51 = DEV_54
PC54 PC90 PC149 PC151 = DEV_58
PC56 PC111 PC133 PC143 PC169 = DEV_198
PC59 = DEV_57
PC63 PC87 PC88 PC113 PC114 PC131 PC132 PC142 PC147 PC161 PC163 PC198 = DEV_251
PC64 = DEV_74
PC66 = DEV_59
PC74 PC219 = DEV_190
PC76 = DEV_283
PC79 = DEV_282
PC81 = DEV_188
PC82 = DEV_187
PC83 = DEV_281
PC84 PC118 PC121 PC135 PC139 PC145 PC152 = DEV_195
PC85 = DEV_186
PC94 PC122 PC153 PC199 = DEV_194
PC95 PC96 PC105-PC110 PC221 PC222 = DEV_274
PC97-PC104 PC164-PC167 = DEV_252
PC116 PC123 PC125 PC126 PC129 PC134 PC196 PC202 PC203 = DEV_197
PC127 PC140 PC154 PC172 = DEV_53
PC144 = DEV_51
PC168 = DEV_193
PC189 = DEV_294
PCE1-PCE3 PCE5 PCE6 = DEV_185
PD1 PD2 = DEV_144
PD5 = DEV_227
PD6 PD7 = DEV_301
PD8 = DEV_111
PF1 = DEV_99
PJP2-PJP16 PR234 = DEV_184
PL1-PL5 = DEV_271
PL7 PL8 = DEV_110
PL9 = DEV_113
PL10 = DEV_303
PL12 = DEV_255
PL13 PL15 PL17 PL19 = DEV_50
PL14 PL16 = DEV_183
PL18 = DEV_182
PL20 = DEV_181
PQ1 PQ24 PQ27 PQ33 PQ36 Q21 = DEV_21
PQ5 PQ6 PQ9 PQ10 PQ13 Q3 Q5 Q7 Q27 Q29-Q31 Q40 Q9200 SQ1 SQ2 = DEV_49
PQ11 = DEV_127
PQ12 PQ14-PQ22 PQ30 = DEV_128
PQ25 PQ31 PQ32 PQ35 = DEV_47
PQ26 PQ34 = DEV_137
PR2 = DEV_167
PR8 PR91 PR141 PR153 R220 R221 = DEV_39
PR13 PR52 PR53 PR124 PR132 R174 R175 R229 R275 R296 R298 R304 R305 R314 R320 R347 = DEV_270
PR55-PR57 = DEV_28
PR58 = DEV_31
PR59-PR66 = DEV_140
PR67 PR68 R99 R125 R127 R341 R344 R369-R371 = DEV_30
PR69 PR70 PR174 PR189 R71 R79-R89 R92-R94 R96-R98 R109 R119 R133 R134 R145 R146 R148 R310 R400 R401 R405 R416 R425-R427 R60358 SR9 SR13 SR14 SR29 SR77-SR82 SR9208 = DEV_41
PR71 PR72 = DEV_19
PR73 = DEV_133
PR74 PR92 = DEV_104
PR75 PR76 PR84 = DEV_38
PR78 = DEV_37
PR79 = DEV_166
PR80 = DEV_34
PR81 PR82 PR233 = DEV_36
PR83 R72 = DEV_35
PR85 = DEV_315
PR86 PR94 PR140 PR143 PR151 PR156 PR166 PR169 R294 R295 = DEV_43
PR87 = DEV_33
PR88-PR90 PR134 PR236 PR239 PR241 R91 R144 R217 R279-R281 R307-R309 R428-R430 R60464 R60472 R60473 R60476 = DEV_83
PR95 PR176 = DEV_29
PR96 = DEV_244
PR97 PR103 = DEV_280
PR98 = DEV_165
PR99 = DEV_164
PR100 = DEV_180
PR106 PR114 PR144 PR172 R131 SR16 SR21 SR97 = DEV_2
PR111 = DEV_293
PR112 = DEV_179
PR113 = DEV_279
PR116 = DEV_250
PR119 = DEV_178
PR120 = DEV_177
PR122 = DEV_176
PR123 = DEV_284
PR125 = DEV_278
PR126 R74 R77 R60365 = DEV_277
PR127 = DEV_292
PR128 PR133 = DEV_175
PR129 = DEV_249
PR136 = DEV_276
PR137 PR142 PR167 PR214 = DEV_173
PR138 PR139 PR150 PR160 = DEV_174
PR146 = DEV_32
PR147 = DEV_172
PR148 PR159 PR182 PR184 R189 R206 R219 R340 R345 R435 SR2 = DEV_45
PR149 PR152 = DEV_248
PR158 = DEV_171
PR161 R232 R234 = DEV_26
PR164 = DEV_27
PR165 = DEV_247
PR168 = DEV_23
PR173 = DEV_300
PR175 = DEV_273
PR178 = DEV_246
PR181 = DEV_245
PR185 = DEV_266
PR186 = DEV_265
PR191 = DEV_170
PR195 PR206 PR223 PR238 = DEV_91
PR196 R436 = DEV_169
PR198 = DEV_291
PR199 PR226 = DEV_168
PR207 PR212 PR235 R222 R223 R236 = DEV_42
PR224 = DEV_290
PRT1-PRT3 = DEV_22
PRT4 = DEV_289
PRT5 = DEV_163
PU3 = DEV_161
PU4 = DEV_264
PU5 = DEV_288
PU6 = DEV_160
PU7 = DEV_159
PU8 = DEV_309
PU9 = DEV_162
Q1 = DEV_94
Q2 Q4 Q12 Q22 Q23 Q35 Q37 = DEV_20
Q6 = DEV_136
Q24 = DEV_158
R1-R26 = DEV_157
R27 R28 = DEV_237
R29 = DEV_154
R30-R37 = DEV_153
R38 = DEV_225
R40 R41 R44 R45 R56 R57 R60 R61 = DEV_239
R42 = DEV_236
R43 = DEV_269
R59 R66 = DEV_150
R69 R76 R78 R103 R106 R9330 SR1 = DEV_18
R70 = DEV_90
R73 = DEV_89
R75 = DEV_130
R95 R124 R128 = DEV_156
R108 = DEV_86
R110 R165 R171 R172 R181 R184 R188 R205 R207 R211 R216 R235 R348 R434 R455-R457 R60368 R60369 R60471 R60477 = DEV_14
R114 R248 = DEV_40
R132 = DEV_155
R135 R137 = DEV_151
R136 R138 R164 R190 R191 R203 R306 R323-R338 R450 = DEV_93
R166-R170 R178 R182 R183 R185 R186 = DEV_88
R173 R176 R193-R202 R204 R251-R256 R354 R355 = DEV_101
R177 R187 R192 R284 R285 SP1 SR9206 = DEV_87
R179 R180 R273 R274 = DEV_17
R210 = DEV_13
R213 R215 = DEV_16
R214 = DEV_15
R218 = DEV_12
R224 R225 R244 R351 R352 R376 R378-R389 R414 R415 R440 = DEV_9
R230 R313 R315 R316 R318 R319 R321 R322 R432 R433 = DEV_8
R231 R233 = DEV_84
R237-R243 R245 R246 = DEV_92
R249 = DEV_299
R282 = DEV_314
R299 = DEV_11
R302 = DEV_10
R311 = DEV_152
R312 = DEV_308
R339 R343 = DEV_46
R342 R346 = DEV_123
R377 = DEV_307
R406 R407 = DEV_254
R431 = DEV_268
R437 = DEV_285
R9203 = DEV_42: room: CTL
R9204 = DEV_243: room: CTL
R60359 R60362 R60370 R60371 VR1 = DEV_85
R60364 S1R4 S1R5 = DEV_258
RN1 RN3 = DEV_5
RN4 = DEV_4
RN6 RN7 = DEV_6
SC1 = DEV_75
SC2-SC6 = DEV_69
SR71 SR72 = DEV_224
SW1 = DEV_106
T30 T34 T53 T9208 = DEV_145
U1 = DEV_305
U2-U5 = DEV_304
U6 = DEV_148
U9 = DEV_135
U10 = DEV_149
U11 = DEV_143
U12 = DEV_109
U13 U14 = DEV_134
U15 = DEV_120
U16 = DEV_313
U17 = DEV_257
U19 = DEV_107
U20 = DEV_306
U21 = DEV_275
U22-U25 = DEV_256
UA3 = DEV_312
VR2 = DEV_97
VU1-VU5 = DEV_125
X1 X2 = DEV_1
X3 = DEV_147
XDP1 = DEV_146

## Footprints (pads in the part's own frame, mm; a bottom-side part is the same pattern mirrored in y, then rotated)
3MM_OPEN_5MIL_M1M2
  custom 0.476x0.476 smd: 1(0,0.317) 2(0,-1.714)
MX_2R4P0402
  rect 0.254x0.66 smd: 1(-0.325,-0.575) 2(-0.325,0.575) 3(0.325,-0.575) 4(0.325,0.575)
MX_2R4P0402_H18
  rect 0.254x0.66 smd: 1(-0.325,-0.575) 2(-0.325,0.575) 3(0.325,-0.575) 4(0.325,0.575)
MX_2R4P0603
  rect 0.508x0.838 smd: 1(-0.4,-0.825) 2(-0.4,0.825) 3(0.4,-0.825) 4(0.4,0.825)
MX_4R8P0402
  rect 0.498x0.61 smd: 1(-0.852,-0.495) 2(-0.852,0.495) 7(0.852,-0.495) 8(0.852,0.495)
  rect 0.295x0.61 smd: 3(-0.25,-0.495) 4(-0.25,0.495) 5(0.25,-0.495) 6(0.25,0.495)
MX_ANT_CLIP_1P_102X107
  custom 0.358x0.358 smd: 1(0,0)
MX_BGA_96P_31_524X433_COLAY
  round 0.406 smd: A1(-6,-3.2) A2(-6,-2.4) A3(-6,-1.6) A7(-6,1.6) A8(-6,2.4) B1(-5.2,-3.2) B8(-5.2,2.4) B9(-5.2,3.2) C8(-4.4,2.4) C9(-4.4,3.2) D9(-3.6,3.2) E9(-2.8,3.2) F8(-2,2.4) F9(-2,3.2) G1(-1.2,-3.2) G9(-1.2,3.2) P1(4.4,-3.2) R3(5.2,-1.6) T1(6,-3.2) T3(6,-1.6) T8(6,2.4) T9(6,3.2)
  round 0.356 smd: A9(-6,3.2) B2(-5.2,-2.4) B3(-5.2,-1.6) B7(-5.2,1.6) C1(-4.4,-3.2) C2(-4.4,-2.4) C3(-4.4,-1.6) C7(-4.4,1.6) D1(-3.6,-3.2) D2(-3.6,-2.4) D3(-3.6,-1.6) D7(-3.6,1.6) D8(-3.6,2.4) E1(-2.8,-3.2) E2(-2.8,-2.4) E3(-2.8,-1.6) E7(-2.8,1.6) E8(-2.8,2.4) F1(-2,-3.2) F2(-2,-2.4) F3(-2,-1.6) F7(-2,1.6) G2(-1.2,-2.4) G3(-1.2,-1.6) G7(-1.2,1.6) G8(-1.2,2.4) H1(-0.4,-3.2) H2(-0.4,-2.4) H3(-0.4,-1.6) H7(-0.4,1.6) H8(-0.4,2.4) H9(-0.4,3.2) J1(0.4,-3.2) J2(0.4,-2.4) J3(0.4,-1.6) J7(0.4,1.6) J8(0.4,2.4) J9(0.4,3.2) K1(1.2,-3.2) K2(1.2,-2.4) K3(1.2,-1.6) K7(1.2,1.6) K8(1.2,2.4) K9(1.2,3.2) L1(2,-3.2) L2(2,-2.4) L3(2,-1.6) L7(2,1.6) L8(2,2.4) L9(2,3.2) M1(2.8,-3.2) M2(2.8,-2.4) M3(2.8,-1.6) M7(2.8,1.6) M8(2.8,2.4) M9(2.8,3.2) N1(3.6,-3.2) N2(3.6,-2.4) N3(3.6,-1.6) N7(3.6,1.6) N8(3.6,2.4) N9(3.6,3.2) P2(4.4,-2.4) P3(4.4,-1.6) P7(4.4,1.6) P8(4.4,2.4) P9(4.4,3.2) R1(5.2,-3.2) R2(5.2,-2.4) R7(5.2,1.6) R8(5.2,2.4) R9(5.2,3.2) T2(6,-2.4) T7(6,1.6)
MX_BGA_1168P_30_1575X945
  round 0.508 smd: A3(18.177,-11.314) A62(-18.722,-11.314) AW1(19.314,10.727) AW63(-19.314,10.743) AY2(18.771,11.314) AY62(-18.748,11.314) B2(18.806,-10.806) B63(-19.314,-10.722) C1(19.314,-10.177)
  oval 0.356x0.457 smd: A4(17.421,-11.314) A5(16.76,-11.314) A6(15.564,-11.314) A59(-16.586,-11.314) A60(-17.412,-11.314) A61(-18.072,-11.314) AY3(18.047,11.314) AY4(17.387,11.314) AY5(16.726,11.314) AY59(-16.774,11.314) AY60(-17.434,11.314) AY61(-18.095,11.314)
  oval 0.279x0.406 smd: A8(14.776,-11.314) A9(13.862,-11.314) A11(12.948,-11.314) A12(12.198,-11.314) A14(11.284,-11.314) A15(10.37,-11.314) A17(9.62,-11.314) A18(8.706,-11.314) A20(7.791,-11.314) AY6(15.939,11.314) AY7(15.189,11.314) AY8(14.44,11.314) AY10(13.691,11.314) AY11(12.942,11.314) AY12(12.192,11.314) AY14(11.443,11.314) AY15(10.694,11.314) AY34(-0.71,11.314) AY35(-1.535,11.314) AY36(-2.284,11.314) AY37(-3.11,11.314) AY39(-3.859,11.314) AY40(-4.685,11.314) AY41(-5.434,11.314) AY42(-6.26,11.314) AY43(-7.009,11.314) AY44(-7.834,11.314) AY46(-8.584,11.314) AY47(-9.409,11.314) AY49(-10.158,11.314) AY50(-10.984,11.314)
  oval 0.267x0.305 smd: A21(7.042,-11.314) A23(6.128,-11.314)
  round 0.33 smd: A24(5.291,-10.989) A28(2.783,-10.989) A32(0.276,-10.989) A36(-2.232,-10.989) A44(-7.247,-10.989) AA2(18.664,0.402) AK22(6.659,4.952) AK23(5.786,4.952) AK25(4.81,4.952) AK26(3.858,4.952) AK28(2.905,4.952) AK29(2.004,4.952) AK32(0.49,4.952) AK33(-0.412,4.952) AK35(-1.415,4.952) AK36(-2.266,4.952) AK38(-3.295,4.952) AK40(-4.792,4.952) AK42(-5.63,4.952) AK43(-6.582,4.952) AK45(-7.56,4.952) AK46(-8.462,4.952) AK48(-9.516,4.952) AK49(-10.418,4.952) AK51(-11.421,4.952) AK52(-12.269,4.952) AK54(-13.295,4.952) AK55(-14.248,4.952) AK57(-15.195,4.952) AK58(-16.094,4.952) AP2(18.664,7.895) B6(15.196,-10.672) B8(14.423,-10.672) B11(12.617,-10.672) B12(11.845,-10.672) B15(10.039,-10.672) B17(9.267,-10.672) B18(8.442,-10.672) B20(7.461,-10.672) B22(6.689,-10.672) B23(5.864,-10.672) B27(3.474,-10.664) B39(-4.049,-10.664) B43(-6.556,-10.664) B45(-7.937,-10.664) B57(-15.459,-10.664) B60(-17.351,-10.654) G2(18.664,-7.091) J2(18.664,-6.341) U2(18.664,-1.846)
  oval 0.279x0.381 smd: A25(4.6,-11.314) A27(3.474,-11.314) A29(2.093,-11.314) A31(0.966,-11.314) A33(-0.415,-11.314) A35(-1.541,-11.314) A37(-2.922,-11.314) A39(-4.049,-11.314) A41(-5.43,-11.314) A43(-6.556,-11.314) A45(-7.937,-11.314) A47(-9.064,-11.314) A49(-10.444,-11.314) A51(-11.571,-11.314) A53(-12.952,-11.314) A55(-14.079,-11.314) A57(-15.459,-11.314) AY17(9.454,11.314) AY19(8.103,11.314) AY21(7.023,11.314) AY23(5.672,11.314) AY25(4.321,11.314) AY27(2.97,11.314) AY29(1.89,11.314) AY31(0.539,11.314) AY52(-12.342,11.314) AY54(-13.693,11.314) AY56(-14.772,11.314) AY58(-16.124,11.314)
  round 0.279 smd: A40(-4.739,-10.989) A48(-9.754,-10.989) A52(-12.262,-10.989) A56(-14.769,-10.989) AA62(-18.664,0.362) AD62(-18.664,1.861) AE62(-18.664,2.61) AG62(-18.339,3.288) AG63(-18.989,3.288) AH62(-18.664,3.964) AJ62(-18.339,4.64) AJ63(-18.989,4.64) AK62(-18.664,5.315) AL2(18.664,5.647) AM2(18.664,6.397) AM62(-18.664,6.395) AN2(18.664,7.146) AN62(-18.339,7.07) AN63(-18.989,7.07) AP62(-18.664,7.746) AR29(1.953,8.203) AT2(18.664,8.645) AV34(-0.71,10.014) AV35(-1.535,10.014) AV36(-2.284,10.014) AV37(-3.11,10.014) AV39(-3.859,10.014) AV40(-4.685,10.014) AV41(-5.434,10.014) AV42(-6.26,10.014) AV43(-7.009,10.014) AV44(-7.834,10.014) AV46(-8.584,10.014) AV47(-9.409,10.014) AV49(-10.158,10.014) AV50(-10.984,10.014) AW5(16.688,10.664) AW6(15.939,10.664) AW16(10.092,10.339) AW17(9.454,10.664) AW18(8.778,10.339) AW19(8.103,10.664) AW21(7.023,10.664) AW22(6.348,10.339) AW23(5.672,10.664) AW24(4.996,10.339) AW25(4.321,10.664) AW26(3.645,10.339) AW27(2.97,10.664) AW29(1.89,10.664) AW30(1.214,10.339) AW31(0.539,10.664) AW33(-0.137,10.339) AW34(-0.71,10.664) AW35(-1.535,10.664) AW36(-2.284,10.664) AW37(-3.11,10.664) AW39(-3.859,10.664) AW40(-4.685,10.664) AW41(-5.434,10.664) AW42(-6.26,10.664) AW43(-7.009,10.664) AW44(-7.834,10.664) AW46(-8.584,10.664) AW47(-9.409,10.664) AW49(-10.158,10.664) AW50(-10.984,10.664) AW51(-11.666,10.339) AW52(-12.342,10.664) AW53(-13.017,10.339) AW54(-13.693,10.664) AW56(-14.772,10.664) AW57(-15.448,10.339) AW58(-16.124,10.664) AY16(10.13,10.989) AY18(8.778,10.989) AY22(6.348,10.989) AY24(4.996,10.989) AY26(3.645,10.989) AY30(1.214,10.989) AY33(-0.137,10.989) AY51(-11.666,10.989) AY53(-13.017,10.989) AY57(-15.448,10.989) B24(5.291,-10.339) B25(4.6,-10.664) B26(4.037,-10.339) B28(2.783,-10.339) B29(2.093,-10.664) B30(1.53,-10.339) B31(0.966,-10.664) B32(0.276,-10.339) B33(-0.415,-10.664) B34(-0.978,-10.339) B35(-1.541,-10.664) B36(-2.232,-10.339) B37(-2.922,-10.664) B38(-3.485,-10.339) B40(-4.739,-10.339) B41(-5.43,-10.664) B42(-5.993,-10.339) B44(-7.247,-10.339) B46(-8.5,-10.339) B47(-9.064,-10.664) B48(-9.754,-10.339) B49(-10.444,-10.664) B50(-11.008,-10.339) B51(-11.571,-10.664) B52(-12.262,-10.339) B53(-12.952,-10.664) B54(-13.515,-10.339) B55(-14.079,-10.664) B56(-14.769,-10.339) J62(-18.664,-6.381) K62(-18.664,-5.632) N62(-18.664,-4.134) P62(-18.664,-3.384) Y62(-18.664,-0.387)
  oval 0.406x0.279 smd: AA1(19.314,0.402) AA63(-19.314,0.362) AC1(19.314,1.152) AC63(-19.314,1.112) AD1(19.314,1.901) AD63(-19.314,1.861) AF1(19.314,2.65) AG1(19.314,3.4) AH1(19.314,4.149) AK1(19.314,4.898) AL1(19.314,5.647) AM1(19.314,6.397) AN1(19.314,7.146) AP1(19.314,7.895) F63(-19.314,-7.88) G1(19.314,-7.091) H63(-19.314,-7.131) J1(19.314,-6.341) J63(-19.314,-6.381) K1(19.314,-5.592) K63(-19.314,-5.632) L1(19.314,-4.843) L63(-19.314,-4.883) N1(19.314,-4.093) N63(-19.314,-4.134) P1(19.314,-3.344) P63(-19.314,-3.384) T1(19.314,-2.595) T63(-19.314,-2.635) U1(19.314,-1.846) U63(-19.314,-1.886) V1(19.314,-1.096) V63(-19.314,-1.136) Y1(19.314,-0.347) Y63(-19.314,-0.387)
  round 0.305 smd: AA3(18.014,0.364) AA4(17.363,0.364) AA59(-16.713,0.324) AA60(-17.363,0.324) AA61(-18.014,0.324) AB5(16.678,0.738) AB6(16.027,0.738) AB7(15.377,0.738) AB8(14.727,0.738) AC2(18.664,1.152) AC3(18.014,1.19) AC4(17.363,1.19) AC59(-16.713,1.15) AC60(-17.363,1.15) AC61(-18.014,1.15) AC62(-18.664,1.112) AD2(18.664,1.901) AD3(18.014,1.863) AD4(17.363,1.863) AD5(16.678,1.691) AD6(16.027,1.691) AD7(15.377,1.691) AD8(14.727,1.691) AD59(-16.713,1.823) AD60(-17.363,1.823) AD61(-18.014,1.823) AE5(16.678,2.643) AE6(16.027,2.643) AE7(15.377,2.643) AE8(14.727,2.643) AE59(-16.713,2.648) AE60(-17.363,2.648) AE61(-18.014,2.648) AF2(18.664,2.65) AF3(18.014,2.688) AF4(17.363,2.688) AG2(18.664,3.4) AG3(18.014,3.361) AG4(17.363,3.361) AG5(16.678,3.596) AG6(16.027,3.596) AG7(15.377,3.596) AG8(14.727,3.596) AG21(7.359,3.807) AG60(-17.038,3.288) AG61(-17.689,3.288) AH2(18.664,4.149) AH3(18.014,4.187) AH4(17.363,4.187) AH10(13.662,4.162) AH11(12.849,4.162) AH13(12.036,4.162) AH14(11.223,4.162) AH16(10.41,4.162) AH17(9.598,4.162) AH19(8.785,4.162) AH20(7.972,4.162) AH60(-17.363,3.964) AH61(-18.014,3.964) AJ5(16.678,4.548) AJ6(16.027,4.548) AJ7(15.377,4.548) AJ8(14.727,4.548) AJ10(13.662,4.812) AJ11(12.849,4.812) AJ13(12.036,4.812) AJ14(11.223,4.812) AJ60(-17.038,4.64) AJ61(-17.689,4.64) AK2(18.664,4.898) AK3(18.014,4.86) AK4(17.363,4.86) AK8(15.011,5.137) AK18(9.466,4.952) AK20(8.513,4.952) AK21(7.561,4.952) AK60(-17.363,5.209) AK61(-18.014,5.209) AL3(18.014,5.686) AL4(17.363,5.686) AL5(16.413,5.462) AL7(15.575,5.462) AL8(15.011,5.787) AL10(13.657,5.462) AL11(13.093,5.787) AL13(11.738,5.462) AL15(11.174,5.787) AL17(10.092,5.268) AL18(9.466,5.602) AL20(8.513,5.602) AL21(7.561,5.602) AL22(6.608,5.602) AL23(5.786,5.602) AL25(4.81,5.602) AL26(3.858,5.602) AL28(2.905,5.602) AL29(1.953,5.602) AL31(1.054,5.277) AL32(0.49,5.602) AL33(-0.412,5.602) AL35(-1.415,5.602) AL36(-2.266,5.602) AL38(-3.32,5.602) AL39(-4.228,5.277) AL40(-4.817,5.602) AL42(-5.63,5.602) AL43(-6.582,5.602) AL45(-7.56,5.602) AL46(-8.487,5.602) AL48(-9.542,5.602) AL49(-10.443,5.602) AL51(-11.447,5.602) AL52(-12.269,5.602) AL54(-13.295,5.602) AL55(-14.248,5.602) AL57(-15.195,5.602) AL58(-16.094,5.602) AL60(-17.038,5.855) AL61(-17.689,5.855) AM3(18.014,6.359) AM4(17.363,6.359) AM5(16.413,6.112) AM7(15.575,6.112) AM8(15.011,6.437) AM10(13.657,6.112) AM11(13.093,6.437) AM13(11.738,6.112) AM15(11.174,6.437) AM17(10.092,5.919) AM18(9.466,6.252) AM20(8.513,6.252) AM21(7.561,6.252) AM22(6.608,6.252) AM23(5.786,6.252) AM25(4.81,6.252) AM26(3.858,6.252) AM28(2.905,6.252) AM29(1.953,6.252) AM31(1.054,5.927) AM32(0.49,6.252) AM33(-0.412,6.252) AM35(-1.415,6.252) AM36(-2.266,6.252) AM38(-3.32,6.252) AM40(-4.817,6.252) AM42(-5.63,6.252) AM43(-6.582,6.252) AM45(-7.56,6.252) AM46(-8.487,6.252) AM48(-9.542,6.252) AM49(-10.443,6.252) AM51(-11.447,6.252) AM52(-12.269,6.252) AM54(-13.295,6.252) AM55(-14.248,6.252) AM57(-15.195,6.252) AM58(-16.094,6.252) AM60(-17.363,6.501) AM61(-18.014,6.501) AN3(18.014,7.184) AN4(17.363,7.184) AN5(16.413,6.762) AN7(15.575,6.762) AN8(15.011,7.088) AN10(13.657,6.762) AN11(13.093,7.088) AN13(11.738,6.762) AN15(11.174,7.088) AN17(10.092,6.569) AN18(9.466,6.903) AN20(8.513,6.903) AN21(7.561,6.903) AN22(6.608,6.903) AN23(5.786,6.903) AN25(4.81,6.903) AN26(3.858,6.903) AN28(2.905,6.903) AN29(1.953,6.903) AN31(1.054,6.578) AN32(0.49,6.903) AN33(-0.412,6.903) AN35(-1.415,6.903) AN36(-2.266,6.903) AN38(-3.32,6.903) AN39(-4.228,6.578) AN40(-4.817,6.903) AN42(-5.63,6.903) AN43(-6.582,6.903) AN45(-7.56,6.903) AN46(-8.487,6.903) AN48(-9.542,6.903) AN49(-10.443,6.903) AN51(-11.447,6.903) AN52(-12.269,6.903) AN54(-13.295,6.903) AN55(-14.248,6.903) AN57(-15.195,6.903) AN58(-16.094,6.903) AN60(-17.038,7.07) AN61(-17.689,7.07) AP3(18.014,7.857) AP4(17.363,7.857) AP5(16.413,7.413) AP7(15.575,7.413) AP8(15.011,7.738) AP10(13.657,7.413) AP11(13.093,7.738) AP13(11.738,7.413) AP15(11.174,7.738) AP17(10.092,7.219) AP18(9.466,7.553) AP20(8.513,7.553) AP21(7.561,7.553) AP22(6.608,7.553) AP23(5.786,7.553) AP25(4.81,7.553) AP26(3.858,7.553) AP28(2.905,7.553) AP29(1.953,7.553) AP31(1.054,7.228) AP32(0.49,7.553) AP33(-0.412,7.553) AP35(-1.415,7.553) AP36(-2.266,7.553) AP38(-3.32,7.553) AP39(-4.228,7.228) AP40(-4.817,7.553) AP42(-5.63,7.553) AP43(-6.582,7.553) AP45(-7.56,7.553) AP46(-8.487,7.553) AP48(-9.542,7.553) AP49(-10.443,7.553) AP51(-11.447,7.553) AP52(-12.269,7.553) AP54(-13.295,7.553) AP55(-14.248,7.553) AP57(-15.195,7.553) AP58(-16.094,7.553) AP60(-17.363,7.746) AP61(-18.014,7.746) AR5(16.413,8.063) AR7(15.575,8.063) AR8(15.011,8.388) AR10(13.657,8.063) AR11(13.093,8.388) AR13(11.738,8.063) AR15(11.174,8.388) AR17(10.092,7.869) AR18(9.466,8.203) AR20(8.513,8.203) AR21(7.561,8.203) AR22(6.608,8.203) AR23(5.786,8.203) AR25(4.81,8.203) AR26(3.858,8.203) AR28(2.905,8.203) AR31(1.054,7.878) AR32(0.49,8.203) AR33(-0.412,8.203) AR35(-1.415,8.203) AR36(-2.266,8.203) AR38(-3.32,8.203) AR39(-4.228,7.878) AR40(-4.817,8.203) AR42(-5.63,8.203) AR43(-6.582,8.203) AR45(-7.56,8.203) AR46(-8.487,8.203) AR48(-9.542,8.203) AR49(-10.443,8.203) AR51(-11.447,8.203) AR52(-12.269,8.203) AR54(-13.295,8.203) AR55(-14.248,8.203) AR57(-15.195,8.203) AR58(-16.094,8.203) AT3(18.014,8.683) AT4(17.363,8.683) AT5(16.413,8.713) AT7(15.575,8.713) AT10(13.657,8.713) AT13(11.738,8.713) AT35(-1.122,8.905) AT37(-2.697,8.905) AT40(-4.272,8.905) AT42(-5.847,8.905) AT43(-7.422,8.905) AT46(-8.996,8.905) AT49(-10.597,8.933) AT61(-17.689,8.32) AT62(-18.498,8.376) AU2(18.659,9.333) AU3(17.999,9.333) AU4(17.338,9.333) AU6(15.977,9.363) AU7(15.151,9.363) AU8(14.478,9.363) AU10(13.653,9.363) AU11(12.98,9.363) AU12(12.154,9.363) AU14(11.481,9.363) AU15(10.656,9.363) AU16(10.092,9.038) AU17(9.454,9.363) AU18(8.778,9.038) AU19(8.21,9.363) AU20(7.563,9.038) AU21(6.917,9.363) AU22(6.348,9.038) AU23(5.672,9.363) AU24(4.996,9.038) AU25(4.321,9.363) AU26(3.645,9.038) AU27(3.076,9.363) AU28(2.43,9.038) AU29(1.783,9.363) AU30(1.214,9.038) AU31(0.539,9.363) AU33(-0.058,9.016) AU34(-0.66,9.363) AU35(-1.585,9.363) AU36(-2.235,9.363) AU37(-3.16,9.363) AU39(-3.81,9.363) AU40(-4.734,9.363) AU41(-5.385,9.363) AU42(-6.309,9.363) AU43(-6.959,9.363) AU44(-7.884,9.363) AU46(-8.534,9.363) AU47(-9.459,9.363) AU49(-10.109,9.363) AU50(-11.086,9.363) AU51(-11.666,9.038) AU52(-12.342,9.363) AU53(-13.017,9.038) AU54(-13.586,9.363) AU55(-14.233,9.038) AU56(-14.879,9.363) AU57(-15.448,9.038) AU58(-16.124,9.363) AU59(-16.688,9.038) AU60(-17.251,9.363) AU61(-17.963,9.087) AU62(-18.664,9.349) AV3(17.993,9.993) AV4(17.338,9.993) AV5(16.65,10.014) AV6(15.977,10.014) AV7(15.151,10.014) AV8(14.478,10.014) AV10(13.653,10.014) AV11(12.98,10.014) AV12(12.154,10.014) AV14(11.481,10.014) AV15(10.656,10.014) AV16(10.092,9.689) AV17(9.454,10.014) AV18(8.778,9.689) AV19(8.21,10.014) AV20(7.563,9.689) AV21(6.917,10.014) AV22(6.348,9.689) AV23(5.672,10.014) AV24(4.996,9.689) AV25(4.321,10.014) AV26(3.645,9.689) AV27(3.076,10.014) AV28(2.43,9.689) AV29(1.783,10.014) AV30(1.214,9.689) AV31(0.539,10.014) AV33(-0.086,9.689) AV51(-11.666,9.689) AV52(-12.342,10.014) AV53(-13.017,9.689) AV54(-13.586,10.014) AV55(-14.233,9.689) AV56(-14.879,10.014) AV57(-15.448,9.689) AV58(-16.124,10.014) AV59(-16.688,9.689) AV60(-17.251,10.014) AV61(-17.988,9.737) AW4(17.338,10.654) AW7(15.189,10.664) AW8(14.44,10.664) AW10(13.691,10.664) AW11(12.942,10.664) AW12(12.192,10.664) AW14(11.443,10.664) AW15(10.694,10.664) AW59(-16.688,10.339) AW60(-17.251,10.664) B4(17.393,-10.664) B5(16.176,-10.672) B9(13.598,-10.672) B14(11.02,-10.672) B21(7.042,-10.118) B58(-16.023,-10.339) B59(-16.586,-10.664) C3(18.012,-10.012) C4(17.196,-10.042) C5(16.542,-10.118) C6(15.538,-10.118) C8(14.776,-10.118) C9(13.964,-10.118) C11(12.96,-10.118) C12(12.198,-10.118) C14(11.386,-10.118) C15(10.382,-10.118) C17(9.62,-10.118) C18(8.807,-10.118) C20(7.804,-10.118) C21(7.423,-9.529) C22(6.636,-9.529) C23(6.229,-10.118) C24(5.263,-9.282) C25(4.6,-10.014) C26(4.037,-9.689) C27(3.474,-10.014) C28(2.756,-9.282) C29(2.093,-10.014) C30(1.53,-9.689) C31(0.966,-10.014) C32(0.248,-9.282) C33(-0.415,-10.014) C34(-0.978,-9.689) C35(-1.541,-10.014) C36(-2.259,-9.282) C37(-2.922,-10.014) C38(-3.485,-9.689) C39(-4.049,-10.014) C40(-4.767,-9.282) C41(-5.43,-10.014) C42(-5.993,-9.689) C43(-6.556,-10.014) C44(-7.274,-9.282) C45(-7.937,-10.014) C46(-8.5,-9.689) C47(-9.064,-10.014) C48(-9.756,-9.282) C49(-10.444,-10.014) C50(-11.008,-9.689) C51(-11.571,-10.014) C52(-12.264,-9.323) C53(-12.952,-10.014) C54(-13.515,-9.689) C55(-14.079,-10.014) C56(-14.771,-9.323) C57(-15.459,-10.014) C58(-16.023,-9.689) C59(-16.586,-10.014) C61(-17.689,-10.077) D2(18.664,-9.24) D3(18.014,-9.278) D5(16.636,-9.472) D6(15.945,-9.529) D8(15.157,-9.529) D9(14.37,-9.529) D11(13.462,-9.529) D12(12.579,-9.529) D14(11.792,-9.529) D15(10.884,-9.529) D17(10.001,-9.529) D18(9.214,-9.529) D20(8.306,-9.529) D21(7.079,-8.891) D23(5.937,-9.529) D25(4.6,-9.363) D26(4.037,-9.038) D27(3.474,-9.363) D29(2.093,-9.363) D30(1.53,-9.038) D31(0.966,-9.363) D33(-0.415,-9.363) D34(-0.978,-9.038) D35(-1.541,-9.363) D37(-2.922,-9.363) D38(-3.485,-9.038) D39(-4.049,-9.363) D41(-5.43,-9.363) D42(-5.993,-9.038) D43(-6.556,-9.363) D45(-7.937,-9.363) D46(-8.5,-9.038) D47(-9.064,-9.363) D49(-10.444,-9.363) D50(-11.008,-9.038) D51(-11.571,-9.363) D53(-12.952,-9.363) D54(-13.515,-9.038) D55(-14.079,-9.363) D57(-15.459,-9.363) D58(-16.023,-9.038) D59(-16.586,-9.363) D60(-17.363,-9.513) D61(-18.014,-9.513) D62(-18.664,-9.28) E2(18.664,-8.589) E3(18.014,-8.627) E4(17.363,-8.627) E5(16.712,-8.695) E6(15.76,-8.695) E8(14.807,-8.695) E10(13.855,-8.695) E11(12.902,-8.695) E13(11.95,-8.695) E15(10.997,-8.695) E17(10.045,-8.695) E18(9.092,-8.695) E20(8.14,-8.695) E59(-16.713,-8.667) E60(-17.363,-8.667) E61(-18.014,-8.667) E62(-18.664,-8.629) F2(18.664,-7.84) F3(18.014,-7.802) F4(17.363,-7.802) F5(16.712,-8.045) F6(15.76,-8.045) F8(14.807,-8.045) F10(13.855,-8.045) F11(12.902,-8.045) F13(11.95,-8.045) F15(10.997,-8.045) F17(10.045,-8.045) F18(9.092,-8.045) F20(8.14,-8.045) F59(-16.713,-7.842) F60(-17.363,-7.842) F61(-18.014,-7.842) F62(-18.664,-7.88) G3(18.014,-7.129) G4(17.363,-7.129) G5(16.712,-7.395) G6(15.76,-7.395) G8(14.807,-7.395) G10(13.855,-7.395) G11(12.902,-7.395) G13(11.95,-7.395) G15(10.997,-7.395) G17(10.045,-7.395) G18(9.092,-7.395) G20(8.14,-7.395) H5(16.712,-6.745) H6(15.76,-6.745) H8(14.807,-6.745) H10(13.855,-6.745) H11(12.902,-6.745) H13(11.95,-6.745) H15(10.997,-6.745) H17(10.045,-6.745) H18(9.092,-6.745) H20(8.14,-6.745) H59(-16.713,-7.169) H60(-17.363,-7.169) H61(-18.014,-7.169) H62(-18.664,-7.131) J3(18.014,-6.303) J4(17.363,-6.303) J5(16.687,-6.094) J6(15.747,-6.094) J8(14.807,-6.094) J10(13.855,-6.094) J11(12.902,-6.094) J13(11.95,-6.094) J15(10.997,-6.094) J17(10.045,-6.094) J18(9.092,-6.094) J20(8.14,-6.094) J21(7.219,-6.328) J59(-16.713,-6.343) J60(-17.363,-6.343) J61(-18.014,-6.343) K2(18.664,-5.592) K3(18.014,-5.63) K4(17.363,-5.63) K59(-16.713,-5.67) K60(-17.363,-5.67) K61(-18.014,-5.67) L2(18.664,-4.843) L3(18.014,-4.805) L4(17.363,-4.805) L5(16.678,-4.977) L6(16.027,-4.977) L7(15.377,-4.977) L8(14.727,-4.977) L59(-16.713,-4.845) L60(-17.363,-4.845) L61(-18.014,-4.845) L62(-18.664,-4.883) N2(18.664,-4.093) N3(18.014,-4.132) N4(17.363,-4.132) N5(16.678,-4.024) N6(16.027,-4.024) N7(15.377,-4.024) N8(14.727,-4.024) N59(-16.713,-4.172) N60(-17.363,-4.172) N61(-18.014,-4.172) P2(18.664,-3.344) P3(18.014,-3.306) P4(17.363,-3.306) P59(-16.713,-3.346) P60(-17.363,-3.346) P61(-18.014,-3.346) R5(16.678,-3.072) R6(16.027,-3.072) R7(15.377,-3.072) R8(14.727,-3.072) T2(18.664,-2.595) T3(18.014,-2.633) T4(17.363,-2.633) T59(-16.713,-2.673) T60(-17.363,-2.673) T61(-18.014,-2.673) T62(-18.664,-2.635) U3(18.014,-1.807) U4(17.363,-1.807) U5(16.678,-2.119) U6(16.027,-2.119) U7(15.377,-2.119) U8(14.727,-2.119) U59(-16.713,-1.848) U60(-17.363,-1.848) U61(-18.014,-1.848) U62(-18.664,-1.886) V2(18.664,-1.096) V3(18.014,-1.134) V4(17.363,-1.134) V5(16.678,-1.167) V6(16.027,-1.167) V7(15.377,-1.167) V8(14.727,-1.167) V59(-16.713,-1.174) V60(-17.363,-1.174) V61(-18.014,-1.174) V62(-18.664,-1.136) Y2(18.664,-0.347) Y3(18.014,-0.309) Y4(17.363,-0.309) Y5(16.678,-0.214) Y6(16.027,-0.214) Y7(15.377,-0.214) Y8(14.727,-0.214) Y59(-16.713,-0.349) Y60(-17.363,-0.349) Y61(-18.014,-0.349)
  round 0.381 smd: AA9(14.282,0.262) AA21(7.627,0.175) AA23(6.199,0.175) AA58(-16.063,0.015) AB10(13.838,0.738) AB20(8.135,0.582) AB21(7.627,0.988) AB22(6.707,0.582) AB23(6.199,0.988) AB57(-15.743,0.666) AC9(14.282,1.215) AC20(8.135,1.394) AC22(6.707,1.394) AC58(-16.063,1.316) AD10(13.838,1.691) AD21(7.627,1.801) AD23(6.199,1.801) AD57(-15.743,1.966) AE9(14.282,2.167) AE10(13.838,2.643) AE20(8.135,2.207) AE21(7.627,2.614) AE22(6.707,2.207) AE23(6.199,2.614) AE58(-16.063,2.616) AF9(14.282,3.12) AF11(13.255,2.968) AF12(12.442,2.968) AF14(11.63,2.968) AF15(10.817,2.968) AF17(10.004,2.968) AF18(9.191,2.968) AF20(8.378,2.968) AF22(6.707,3.02) AG10(13.662,3.476) AG11(12.849,3.476) AG13(12.036,3.476) AG14(11.223,3.476) AG16(10.41,3.476) AG17(9.598,3.476) AG19(8.785,3.476) AG20(7.972,3.476) AG23(6.199,3.426) AG57(-15.743,3.267) AG58(-16.377,3.695) AH22(6.707,3.833) AH24(5.394,3.975) AH26(4.094,3.975) AH28(2.793,3.975) AH30(1.493,3.975) AH32(0.192,3.975) AH34(-1.108,3.975) AH36(-2.409,3.975) AH38(-3.709,3.975) AH40(-5.01,3.975) AH42(-6.31,3.975) AH44(-7.611,3.975) AH46(-8.911,3.975) AH49(-10.212,3.975) AH51(-11.512,3.975) AH53(-12.813,3.975) AH55(-14.113,3.975) AH57(-15.413,3.975) AJ23(6.199,4.239) AJ25(4.744,4.3) AJ27(3.443,4.3) AJ29(2.143,4.3) AJ31(0.843,4.3) AJ33(-0.458,4.3) AJ35(-1.758,4.3) AJ37(-3.059,4.3) AJ39(-4.359,4.3) AJ41(-5.66,4.3) AJ43(-6.96,4.3) AJ45(-8.261,4.3) AJ47(-9.561,4.3) AJ50(-10.862,4.3) AJ52(-12.162,4.3) AJ54(-13.463,4.3) AJ56(-14.763,4.3) AJ58(-16.064,4.3) AV2(18.654,9.993) AV62(-18.664,10.004) AW61(-18.014,10.664) AW62(-18.664,10.664) B3(18.056,-10.664) B61(-18.001,-10.654) B62(-18.664,-10.59) C2(18.664,-10.056) C62(-18.664,-9.93) E23(5.981,-8.713) E25(4.6,-8.713) E27(3.474,-8.713) E29(2.093,-8.713) E31(0.966,-8.713) E33(-0.415,-8.713) E35(-1.541,-8.713) E37(-2.922,-8.713) E39(-4.049,-8.713) E41(-5.43,-8.713) E43(-6.556,-8.713) E45(-7.937,-8.713) E47(-9.064,-8.713) E49(-10.444,-8.713) E51(-11.571,-8.713) E53(-12.952,-8.713) E55(-14.079,-8.713) E57(-15.459,-8.713) F22(6.597,-8.256) F24(5.291,-8.188) F26(4.037,-8.188) F28(2.783,-8.188) F30(1.53,-8.188) F32(0.276,-8.188) F34(-0.978,-8.188) F36(-2.232,-8.188) F38(-3.485,-8.188) F40(-4.739,-8.188) F42(-5.993,-8.188) F44(-7.247,-8.188) F46(-8.5,-8.188) F48(-9.754,-8.188) F50(-11.008,-8.188) F52(-12.262,-8.188) F54(-13.515,-8.188) F56(-14.769,-8.188) F58(-16.063,-8.188) G22(6.707,-7.546) G23(5.981,-7.863) G25(4.6,-7.863) G27(3.474,-7.863) G29(2.093,-7.863) G31(0.966,-7.863) G33(-0.415,-7.863) G35(-1.541,-7.863) G37(-2.922,-7.863) G39(-4.049,-7.863) G41(-5.43,-7.863) G43(-6.556,-7.863) G45(-7.937,-7.863) G47(-9.064,-7.863) G49(-10.444,-7.863) G51(-11.571,-7.863) G53(-12.952,-7.863) G55(-14.079,-7.863) G57(-15.459,-7.863) H22(6.707,-6.734) H23(6.199,-7.14) H57(-15.743,-7.213) J22(6.707,-5.921) J23(6.199,-6.327) J58(-16.063,-6.487) K9(14.282,-5.453) K10(13.379,-5.614) K12(12.426,-5.614) K14(11.474,-5.614) K16(10.521,-5.614) K18(9.569,-5.614) K19(8.616,-5.614) K21(7.664,-5.614) K23(6.199,-5.514) K57(-15.743,-5.837) L10(13.838,-4.977) L11(12.902,-5.17) L13(11.95,-5.17) L15(10.997,-5.17) L17(10.045,-5.17) L18(9.092,-5.17) L20(8.135,-5.108) L22(6.707,-5.108) L58(-16.063,-5.186) M9(14.282,-4.5) M20(8.135,-4.295) M21(7.627,-4.702) M22(6.707,-4.295) M23(6.199,-4.702) M57(-15.743,-4.536) N10(13.838,-4.024) N21(7.627,-3.889) N23(6.199,-3.889) N58(-16.063,-3.886) P9(14.282,-3.548) P20(8.135,-3.482) P22(6.707,-3.482) P57(-15.743,-3.236) R10(13.838,-3.072) R20(8.135,-2.67) R21(7.627,-3.076) R22(6.707,-2.67) R23(6.199,-3.076) T9(14.282,-2.595) T21(7.627,-2.263) T23(6.199,-2.263) T58(-16.063,-2.585) U9(14.282,-1.643) U10(13.838,-2.119) U20(8.135,-1.857) U22(6.707,-1.857) U57(-15.743,-1.935) V10(13.838,-1.167) V21(7.627,-1.45) V23(6.199,-1.45) V58(-16.063,-1.285) W9(14.282,-0.69) W20(8.135,-1.044) W21(7.627,-0.638) W22(6.707,-1.044) W23(6.199,-0.638) W57(-15.743,-0.635) Y10(13.838,-0.214) Y20(8.135,-0.231) Y22(6.707,-0.231)
  oval 0.381x0.279 smd: AE63(-19.314,2.61) AH63(-19.314,3.964) AK63(-19.314,5.315) AM63(-19.314,6.395) AP63(-19.314,7.746)
  oval 0.457x0.356 smd: AT1(19.314,8.683) AT63(-19.314,8.533) AU1(19.314,9.343) AU63(-19.314,9.359) AV1(19.314,10.004) AV63(-19.314,10.019) C63(-19.314,-9.998) D1(19.314,-9.453) D63(-19.314,-9.338) E1(19.314,-8.792) E63(-19.314,-8.667) F1(19.314,-7.878)
  round 0.368 smd: AW2(18.654,10.654) AW3(17.993,10.654)
